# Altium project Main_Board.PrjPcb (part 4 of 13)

## Sheet SPI_Muxes.SchDoc: SPI_Muxes
size A3; Organization: Altium Limited; Address1: L3, 12a Rodborough Rd; Address2: Frenchs Forest; Address3: NSW; Address4: Australia 2086
Used 2 times, as channels HighSpeed/SPI_bridge_PCIe, SPI_bridge_Main. Parts and nets are listed once, with the designators drawn on the sheet.
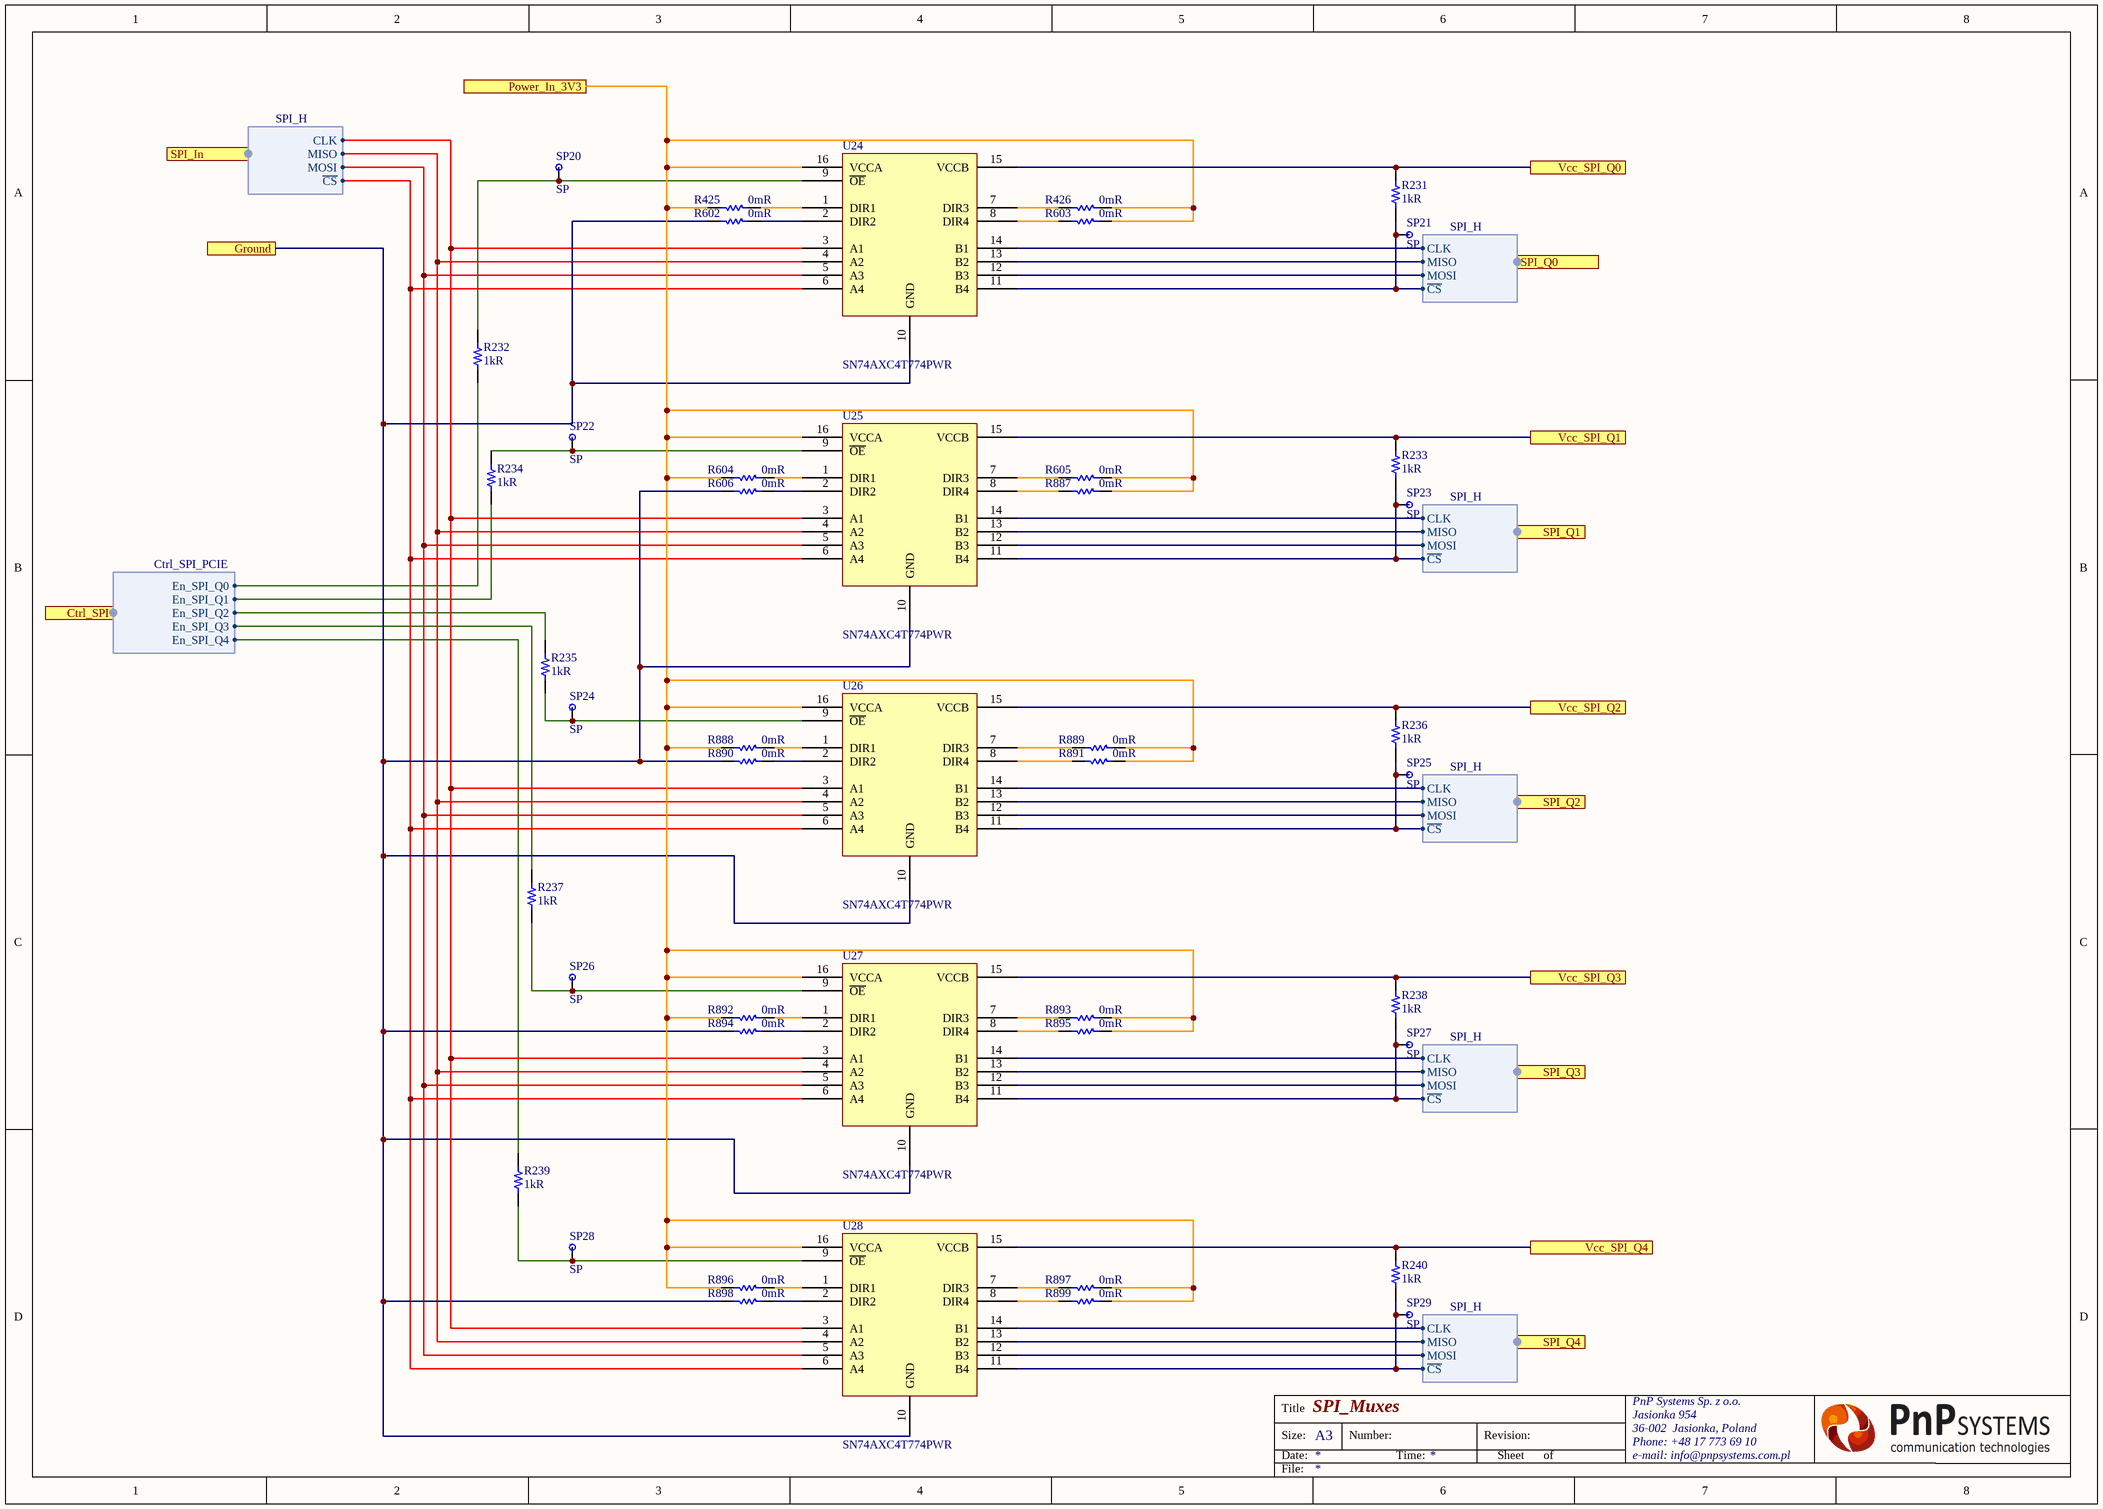
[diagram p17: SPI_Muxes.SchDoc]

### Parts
R231  1kR  [RES 0402/1005 RF KK]
R232  1kR  [RES 0402/1005 RF KK]
R233  1kR  [RES 0402/1005 RF KK]
R234  1kR  [RES 0402/1005 RF KK]
R235  1kR  [RES 0402/1005 RF KK]
R236  1kR  [RES 0402/1005 RF KK]
R237  1kR  [RES 0402/1005 RF KK]
R238  1kR  [RES 0402/1005 RF KK]
R239  1kR  [RES 0402/1005 RF KK]
R240  1kR  [RES 0402/1005 RF KK]
R425  0mR  [RES 0402/1005 RF KK]
R426  0mR  [RES 0402/1005 RF KK]
R602  0mR  [RES 0402/1005 RF KK]
R603  0mR  [RES 0402/1005 RF KK]
R604  0mR  [RES 0402/1005 RF KK]
R605  0mR  [RES 0402/1005 RF KK]
R606  0mR  [RES 0402/1005 RF KK]
R887  0mR  [RES 0402/1005 RF KK]
R888  0mR  [RES 0402/1005 RF KK]
R889  0mR  [RES 0402/1005 RF KK]
R890  0mR  [RES 0402/1005 RF KK]
R891  0mR  [RES 0402/1005 RF KK]
R892  0mR  [RES 0402/1005 RF KK]
R893  0mR  [RES 0402/1005 RF KK]
R894  0mR  [RES 0402/1005 RF KK]
R895  0mR  [RES 0402/1005 RF KK]
R896  0mR  [RES 0402/1005 RF KK]
R897  0mR  [RES 0402/1005 RF KK]
R898  0mR  [RES 0402/1005 RF KK]
R899  0mR  [RES 0402/1005 RF KK]
SP20  SP  [MeasureTP]
SP21  SP  [MeasureTP]
SP22  SP  [MeasureTP]
SP23  SP  [MeasureTP]
SP24  SP  [MeasureTP]
SP25  SP  [MeasureTP]
SP26  SP  [MeasureTP]
SP27  SP  [MeasureTP]
SP28  SP  [MeasureTP]
SP29  SP  [MeasureTP]
U24  SN74AXC4T774PWR  [SN74AXC4T774PWR]
U25  SN74AXC4T774PWR  [SN74AXC4T774PWR]
U26  SN74AXC4T774PWR  [SN74AXC4T774PWR]
U27  SN74AXC4T774PWR  [SN74AXC4T774PWR]
U28  SN74AXC4T774PWR  [SN74AXC4T774PWR]

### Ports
Ctrl_SPI (harness Ctrl_SPI_PCIE), Ground, Power_In_3V3, SPI_In (harness SPI_H), SPI_Q0 (harness SPI_H), SPI_Q1 (harness SPI_H), SPI_Q2 (harness SPI_H), SPI_Q3 (harness SPI_H), SPI_Q4 (harness SPI_H), Vcc_SPI_Q0, Vcc_SPI_Q1, Vcc_SPI_Q2, Vcc_SPI_Q3, Vcc_SPI_Q4

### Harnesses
SPI_H: CLK, MISO, MOSI, ~{CS}
Ctrl_SPI_PCIE: En_SPI_Q0, En_SPI_Q1, En_SPI_Q2, En_SPI_Q3, En_SPI_Q4

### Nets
Ground: R602.2 R606.2 R890.2 R894.2 R898.2 U24.10(GND) U25.10(GND) U26.10(GND) U27.10(GND) U28.10(GND) ; port Ground
Power_In_3V3: R425.2 R426.1 R603.1 R604.2 R605.1 R887.1 R888.2 R889.1 R891.1 R892.2 R893.1 R895.1 R896.2 R897.1 R899.1 U24.16(VCCA) U25.16(VCCA) U26.16(VCCA) U27.16(VCCA) U28.16(VCCA) ; port Power_In_3V3
Vcc_SPI_Q0: R231.2 U24.15(VCCB) ; port Vcc_SPI_Q0
Vcc_SPI_Q1: R233.2 U25.15(VCCB) ; port Vcc_SPI_Q1
Vcc_SPI_Q2: R236.2 U26.15(VCCB) ; port Vcc_SPI_Q2
Vcc_SPI_Q3: R238.2 U27.15(VCCB) ; port Vcc_SPI_Q3
Vcc_SPI_Q4: R240.2 U28.15(VCCB) ; port Vcc_SPI_Q4
NetR231_1: R231.1 SP21.1 U24.11(B4) ; port SPI_Q0.~{CS}
NetR232_1: R232.1 ; port Ctrl_SPI.En_SPI_Q0
NetR232_2: R232.2 SP20.1 U24.9(~{OE})
NetR233_1: R233.1 SP23.1 U25.11(B4) ; port SPI_Q1.~{CS}
NetR234_1: R234.1 ; port Ctrl_SPI.En_SPI_Q1
NetR234_2: R234.2 SP22.1 U25.9(~{OE})
NetR235_1: R235.1 SP24.1 U26.9(~{OE})
NetR235_2: R235.2 ; port Ctrl_SPI.En_SPI_Q2
NetR236_1: R236.1 SP25.1 U26.11(B4) ; port SPI_Q2.~{CS}
NetR237_1: R237.1 SP26.1 U27.9(~{OE})
NetR237_2: R237.2 ; port Ctrl_SPI.En_SPI_Q3
NetR238_1: R238.1 SP27.1 U27.11(B4) ; port SPI_Q3.~{CS}
NetR239_1: R239.1 ; port Ctrl_SPI.En_SPI_Q4
NetR239_2: R239.2 SP28.1 U28.9(~{OE})
NetR240_1: R240.1 SP29.1 U28.11(B4) ; port SPI_Q4.~{CS}
NetR425_1: R425.1 U24.1(DIR1)
NetR426_2: R426.2 U24.7(DIR3)
NetR602_1: R602.1 U24.2(DIR2)
NetR603_2: R603.2 U24.8(DIR4)
NetR604_1: R604.1 U25.1(DIR1)
NetR605_2: R605.2 U25.7(DIR3)
NetR606_1: R606.1 U25.2(DIR2)
NetR887_2: R887.2 U25.8(DIR4)
NetR888_1: R888.1 U26.1(DIR1)
NetR889_2: R889.2 U26.7(DIR3)
NetR890_1: R890.1 U26.2(DIR2)
NetR891_2: R891.2 U26.8(DIR4)
NetR892_1: R892.1 U27.1(DIR1)
NetR893_2: R893.2 U27.7(DIR3)
NetR894_1: R894.1 U27.2(DIR2)
NetR895_2: R895.2 U27.8(DIR4)
NetR896_1: R896.1 U28.1(DIR1)
NetR897_2: R897.2 U28.7(DIR3)
NetR898_1: R898.1 U28.2(DIR2)
NetR899_2: R899.2 U28.8(DIR4)
NetU24_3: U24.3(A1) U25.3(A1) U26.3(A1) U27.3(A1) U28.3(A1) ; port SPI_In.CLK
NetU24_4: U24.4(A2) U25.4(A2) U26.4(A2) U27.4(A2) U28.4(A2) ; port SPI_In.MISO
NetU24_5: U24.5(A3) U25.5(A3) U26.5(A3) U27.5(A3) U28.5(A3) ; port SPI_In.MOSI
NetU24_6: U24.6(A4) U25.6(A4) U26.6(A4) U27.6(A4) U28.6(A4) ; port SPI_In.~{CS}
NetU24_12: U24.12(B3) ; port SPI_Q0.MOSI
NetU24_13: U24.13(B2) ; port SPI_Q0.MISO
NetU24_14: U24.14(B1) ; port SPI_Q0.CLK
NetU25_12: U25.12(B3) ; port SPI_Q1.MOSI
NetU25_13: U25.13(B2) ; port SPI_Q1.MISO
NetU25_14: U25.14(B1) ; port SPI_Q1.CLK
NetU26_12: U26.12(B3) ; port SPI_Q2.MOSI
NetU26_13: U26.13(B2) ; port SPI_Q2.MISO
NetU26_14: U26.14(B1) ; port SPI_Q2.CLK
NetU27_12: U27.12(B3) ; port SPI_Q3.MOSI
NetU27_13: U27.13(B2) ; port SPI_Q3.MISO
NetU27_14: U27.14(B1) ; port SPI_Q3.CLK
NetU28_12: U28.12(B3) ; port SPI_Q4.MOSI
NetU28_13: U28.13(B2) ; port SPI_Q4.MISO
NetU28_14: U28.14(B1) ; port SPI_Q4.CLK

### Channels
HighSpeed/SPI_bridge_PCIe: designators end in _SPI_bridge_PCIe; ports Ground=B503_Ground Power_In_3V3=3V3_RAIL Vcc_SPI_Q0=3V3_RAIL Vcc_SPI_Q1=3V3_RAIL Vcc_SPI_Q2=3V3_RAIL Vcc_SPI_Q3=3V3_RAIL Vcc_SPI_Q4=3V3_RAIL
SPI_bridge_Main: designators end in _SPI_bridge_Main; ports Ground=B503_Ground Power_In_3V3=3V3_RAIL Vcc_SPI_Q0=3V3_RAIL Vcc_SPI_Q1=3V3_RAIL Vcc_SPI_Q2=3V3_RAIL Vcc_SPI_Q3=3V3_RAIL Vcc_SPI_Q4=3V3_RAIL

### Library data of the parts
R231-R240 = Resistor: Manufacturer: Panasonic; Manufacturer Part Number: ERJ-2RKF1001X; Tolerance: 1%; Power Rating: 100mW; Temperature Coefficient: 100ppm/°C; Voltage Rating: 50V
R425 R426 R602-R606 R887-R899 = Resistor: Manufacturer 1: Yageo; Manufacturer Part Number 1: RC0402JR-070RL; Power Rating: 62.5mW; Tolerance: 5%; Voltage Rating: 50V; Max Power Dissipation: 63mW; Temperature Coefficient: 200ppm/°C
U24-U28 = SN74AXC4T774PWR: Manufacturer 1: Texas Instruments

## Sheet Power4HiSpeed.SchDoc
size A3; Organization: Altium Limited; Address1: L3, 12a Rodborough Rd; Address2: Frenchs Forest; Address3: NSW; Address4: Australia 2086
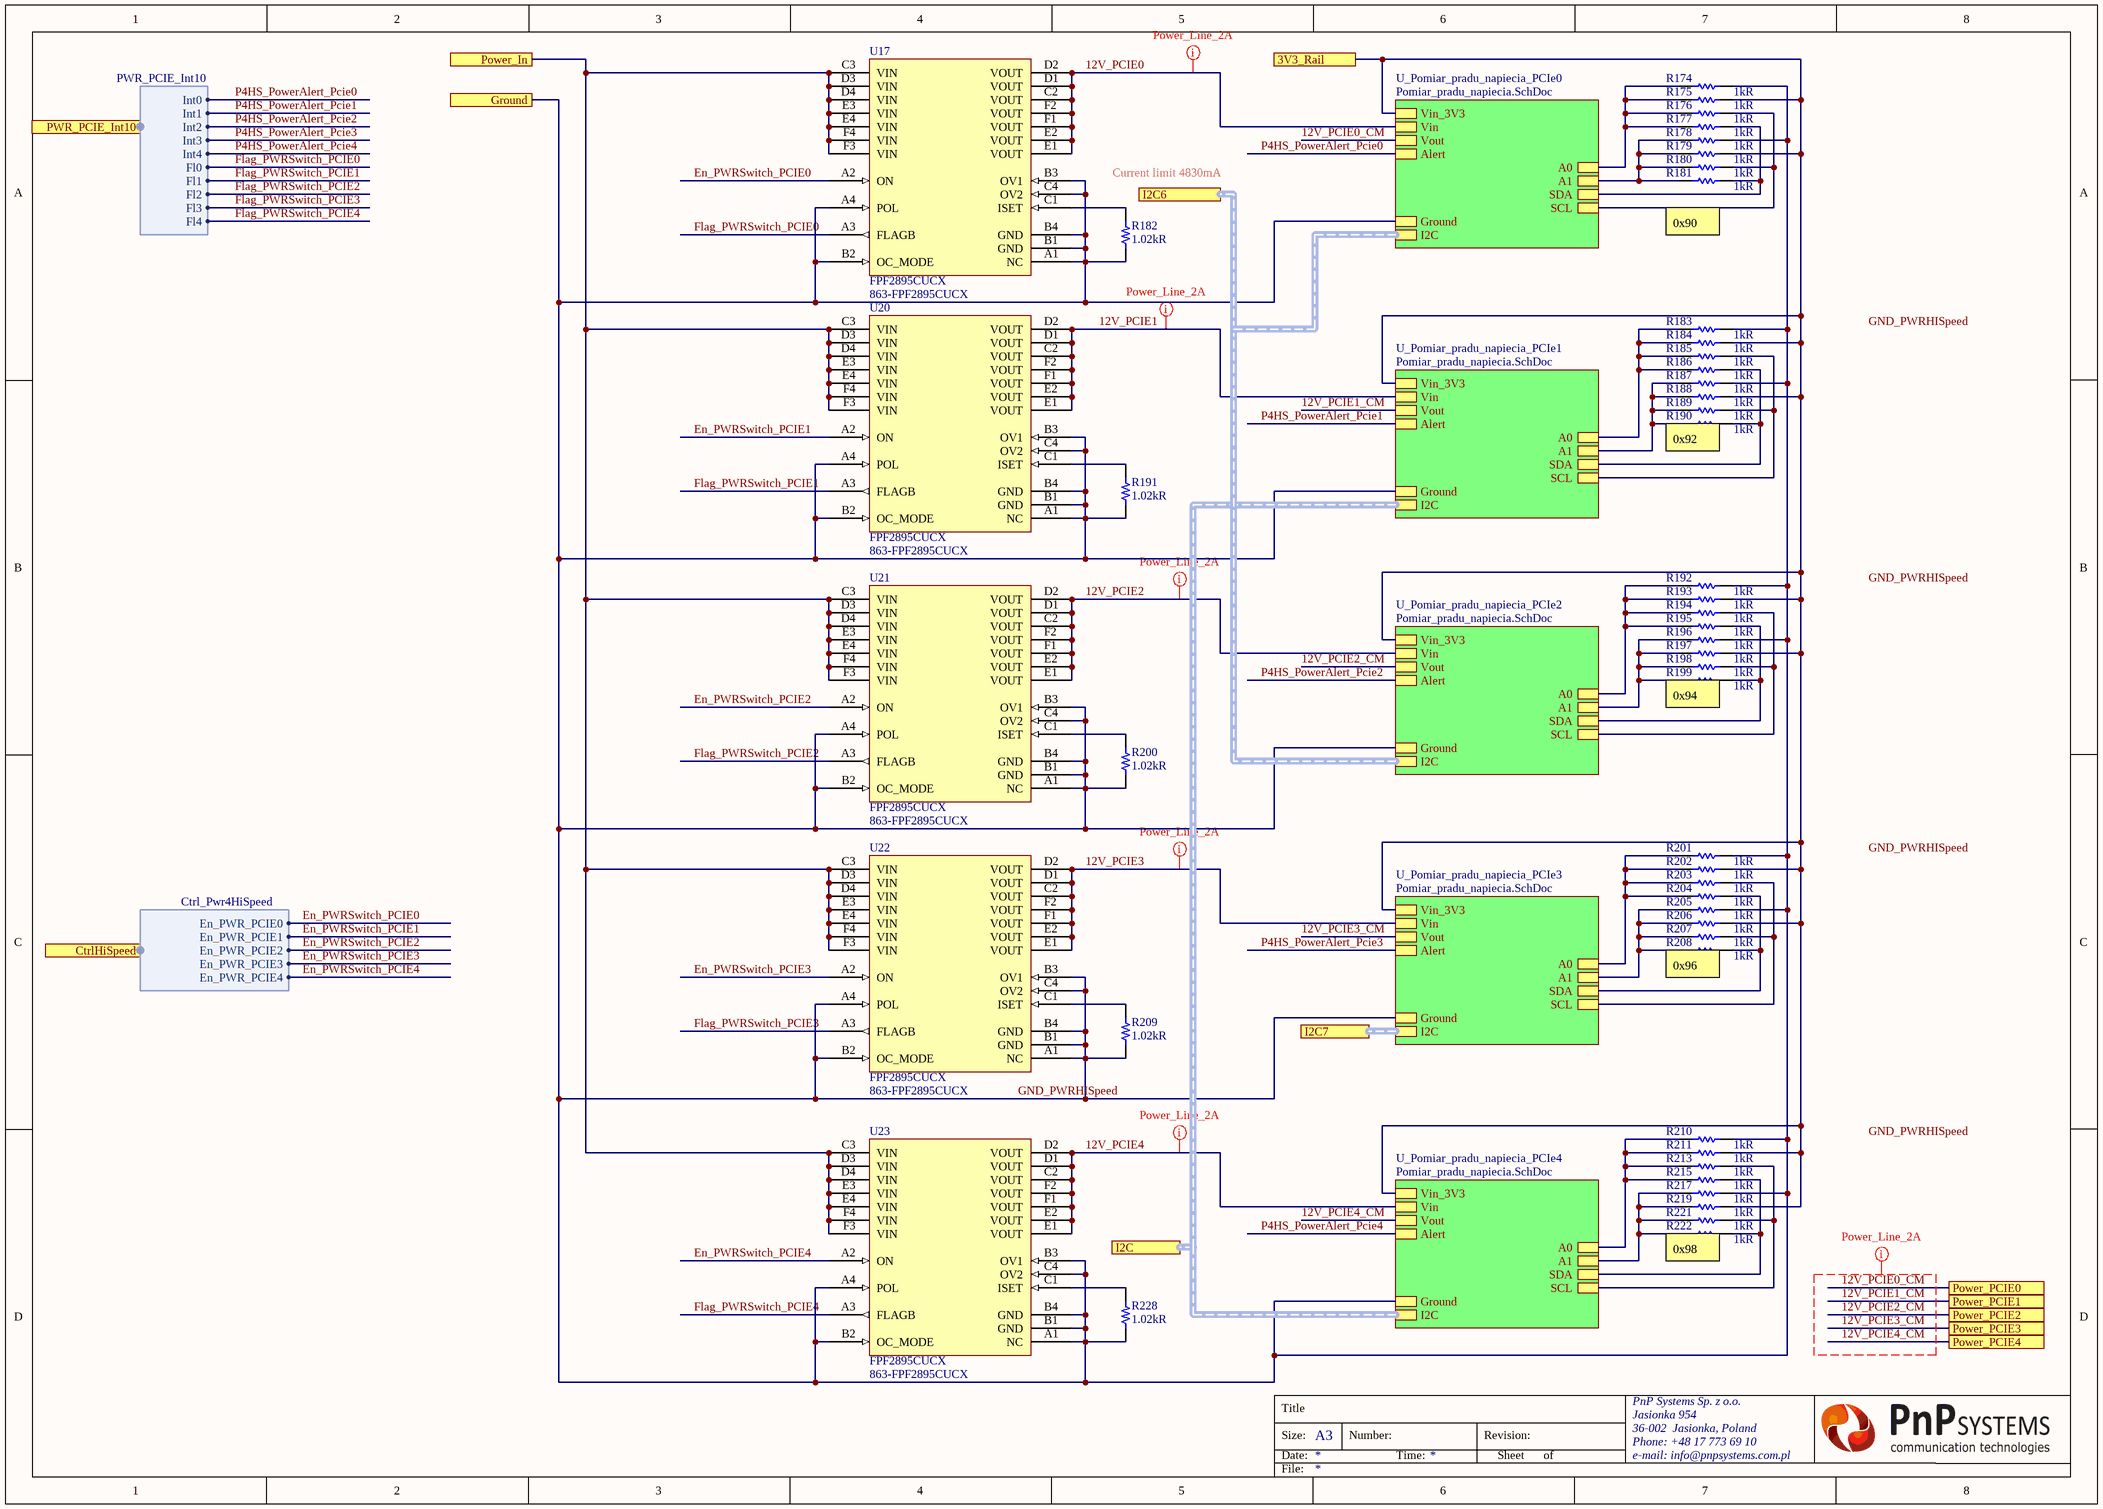
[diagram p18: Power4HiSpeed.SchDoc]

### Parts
R174  1kR  [RES 0402/1005 RF KK]
R175  1kR  [RES 0402/1005 RF KK]
R176  1kR  [RES 0402/1005 RF KK]
R177  1kR  [RES 0402/1005 RF KK]
R178  1kR  [RES 0402/1005 RF KK]
R179  1kR  [RES 0402/1005 RF KK]
R180  1kR  [RES 0402/1005 RF KK]
R181  1kR  [RES 0402/1005 RF KK]
R182  1.02kR  [RES 0402/1005 RF KK]
R183  1kR  [RES 0402/1005 RF KK]
R184  1kR  [RES 0402/1005 RF KK]
R185  1kR  [RES 0402/1005 RF KK]
R186  1kR  [RES 0402/1005 RF KK]
R187  1kR  [RES 0402/1005 RF KK]
R188  1kR  [RES 0402/1005 RF KK]
R189  1kR  [RES 0402/1005 RF KK]
R190  1kR  [RES 0402/1005 RF KK]
R191  1.02kR  [RES 0402/1005 RF KK]
R192  1kR  [RES 0402/1005 RF KK]
R193  1kR  [RES 0402/1005 RF KK]
R194  1kR  [RES 0402/1005 RF KK]
R195  1kR  [RES 0402/1005 RF KK]
R196  1kR  [RES 0402/1005 RF KK]
R197  1kR  [RES 0402/1005 RF KK]
R198  1kR  [RES 0402/1005 RF KK]
R199  1kR  [RES 0402/1005 RF KK]
R200  1.02kR  [RES 0402/1005 RF KK]
R201  1kR  [RES 0402/1005 RF KK]
R202  1kR  [RES 0402/1005 RF KK]
R203  1kR  [RES 0402/1005 RF KK]
R204  1kR  [RES 0402/1005 RF KK]
R205  1kR  [RES 0402/1005 RF KK]
R206  1kR  [RES 0402/1005 RF KK]
R207  1kR  [RES 0402/1005 RF KK]
R208  1kR  [RES 0402/1005 RF KK]
R209  1.02kR  [RES 0402/1005 RF KK]
R210  1kR  [RES 0402/1005 RF KK]
R211  1kR  [RES 0402/1005 RF KK]
R213  1kR  [RES 0402/1005 RF KK]
R215  1kR  [RES 0402/1005 RF KK]
R217  1kR  [RES 0402/1005 RF KK]
R219  1kR  [RES 0402/1005 RF KK]
R221  1kR  [RES 0402/1005 RF KK]
R222  1kR  [RES 0402/1005 RF KK]
R228  1.02kR  [RES 0402/1005 RF KK]
U17  FPF2895CUCX  Supplier Part Number 1: 863-FPF2895CUCX  [FPF2895C-D]
U20  FPF2895CUCX  Supplier Part Number 1: 863-FPF2895CUCX  [FPF2895C-D]
U21  FPF2895CUCX  Supplier Part Number 1: 863-FPF2895CUCX  [FPF2895C-D]
U22  FPF2895CUCX  Supplier Part Number 1: 863-FPF2895CUCX  [FPF2895C-D]
U23  FPF2895CUCX  Supplier Part Number 1: 863-FPF2895CUCX  [FPF2895C-D]

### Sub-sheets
U_Pomiar_pradu_napiecia_PCIe0 = Pomiar_pradu_napiecia.SchDoc: Vin_3V3, Vin, Vout, Alert, A0, A1, SDA, SCL, Ground, I2C (harness I2C)
U_Pomiar_pradu_napiecia_PCIe1 = Pomiar_pradu_napiecia.SchDoc: Vin_3V3, Vin, Vout, Alert, A0, A1, SDA, SCL, Ground, I2C (harness I2C)
U_Pomiar_pradu_napiecia_PCIe2 = Pomiar_pradu_napiecia.SchDoc: Vin_3V3, Vin, Vout, Alert, A0, A1, SDA, SCL, Ground, I2C (harness I2C)
U_Pomiar_pradu_napiecia_PCIe3 = Pomiar_pradu_napiecia.SchDoc: Vin_3V3, Vin, Vout, Alert, A0, A1, SDA, SCL, Ground, I2C (harness I2C)
U_Pomiar_pradu_napiecia_PCIe4 = Pomiar_pradu_napiecia.SchDoc: Vin_3V3, Vin, Vout, Alert, A0, A1, SDA, SCL, Ground, I2C (harness I2C)

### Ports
3V3_Rail, CtrlHiSpeed (harness Ctrl_Pwr4HiSpeed), Ground, I2C6, I2C7, I2C (harness I2C), Power_In, Power_PCIE0, Power_PCIE1, Power_PCIE2, Power_PCIE3, Power_PCIE4, PWR_PCIE_Int10 (harness PWR_PCIE_Int10)

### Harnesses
Ctrl_Pwr4HiSpeed: En_PWR_PCIE0, En_PWR_PCIE1, En_PWR_PCIE2, En_PWR_PCIE3, En_PWR_PCIE4
PWR_PCIE_Int10: Int0, Int1, Int2, Int3, Int4, Fl0, Fl1, Fl2, Fl3, Fl4

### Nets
GND_PWRHISpeed: R174.2 R178.2 R182.1 R183.2 R187.2 R191.1 R192.2 R196.2 R200.1 R201.2 R205.2 R209.1 R210.2 R217.2 R228.1 U17.A1(NC) U17.A4(POL) U17.B1(GND) U17.B2(OC_MODE) U17.B3(OV1) U17.B4(GND) U17.C4(OV2) U20.A1(NC) U20.A4(POL) U20.B1(GND) U20.B2(OC_MODE) U20.B3(OV1) U20.B4(GND) U20.C4(OV2) U21.A1(NC) U21.A4(POL) U21.B1(GND) U21.B2(OC_MODE) U21.B3(OV1) U21.B4(GND) U21.C4(OV2) U22.A1(NC) U22.A4(POL) U22.B1(GND) U22.B2(OC_MODE) U22.B3(OV1) U22.B4(GND) U22.C4(OV2) U23.A1(NC) U23.A4(POL) U23.B1(GND) U23.B2(OC_MODE) U23.B3(OV1) U23.B4(GND) U23.C4(OV2) ; port Ground, sheet U_Pomiar_pradu_napiecia_PCIe0/Ground, sheet U_Pomiar_pradu_napiecia_PCIe1/Ground, sheet U_Pomiar_pradu_napiecia_PCIe2/Ground, sheet U_Pomiar_pradu_napiecia_PCIe3/Ground, sheet U_Pomiar_pradu_napiecia_PCIe4/Ground  [project net B503_Ground]
3V3_RAIL: R175.2 R179.2 R184.2 R188.2 R193.2 R197.2 R202.2 R206.2 R211.2 R219.2 ; port 3V3_Rail, sheet U_Pomiar_pradu_napiecia_PCIe0/Vin_3V3, sheet U_Pomiar_pradu_napiecia_PCIe1/Vin_3V3, sheet U_Pomiar_pradu_napiecia_PCIe2/Vin_3V3, sheet U_Pomiar_pradu_napiecia_PCIe3/Vin_3V3, sheet U_Pomiar_pradu_napiecia_PCIe4/Vin_3V3
12V_LT3042: U17.C3(VIN) U17.D3(VIN) U17.D4(VIN) U17.E3(VIN) U17.E4(VIN) U17.F3(VIN) U17.F4(VIN) U20.C3(VIN) U20.D3(VIN) U20.D4(VIN) U20.E3(VIN) U20.E4(VIN) U20.F3(VIN) U20.F4(VIN) U21.C3(VIN) U21.D3(VIN) U21.D4(VIN) U21.E3(VIN) U21.E4(VIN) U21.F3(VIN) U21.F4(VIN) U22.C3(VIN) U22.D3(VIN) U22.D4(VIN) U22.E3(VIN) U22.E4(VIN) U22.F3(VIN) U22.F4(VIN) U23.C3(VIN) U23.D3(VIN) U23.D4(VIN) U23.E3(VIN) U23.E4(VIN) U23.F3(VIN) U23.F4(VIN) ; port Power_In
12V_PCIE0: U17.C2(VOUT) U17.D1(VOUT) U17.D2(VOUT) U17.E1(VOUT) U17.E2(VOUT) U17.F1(VOUT) U17.F2(VOUT) ; sheet U_Pomiar_pradu_napiecia_PCIe0/Vin
12V_PCIE0_CM: port Power_PCIE0, sheet U_Pomiar_pradu_napiecia_PCIe0/Vout
12V_PCIE1: U20.C2(VOUT) U20.D1(VOUT) U20.D2(VOUT) U20.E1(VOUT) U20.E2(VOUT) U20.F1(VOUT) U20.F2(VOUT) ; sheet U_Pomiar_pradu_napiecia_PCIe1/Vin
12V_PCIE1_CM: port Power_PCIE1, sheet U_Pomiar_pradu_napiecia_PCIe1/Vout
12V_PCIE2: U21.C2(VOUT) U21.D1(VOUT) U21.D2(VOUT) U21.E1(VOUT) U21.E2(VOUT) U21.F1(VOUT) U21.F2(VOUT) ; sheet U_Pomiar_pradu_napiecia_PCIe2/Vin
12V_PCIE2_CM: port Power_PCIE2, sheet U_Pomiar_pradu_napiecia_PCIe2/Vout
12V_PCIE3: U22.C2(VOUT) U22.D1(VOUT) U22.D2(VOUT) U22.E1(VOUT) U22.E2(VOUT) U22.F1(VOUT) U22.F2(VOUT) ; sheet U_Pomiar_pradu_napiecia_PCIe3/Vin
12V_PCIE3_CM: port Power_PCIE3, sheet U_Pomiar_pradu_napiecia_PCIe3/Vout
12V_PCIE4: U23.C2(VOUT) U23.D1(VOUT) U23.D2(VOUT) U23.E1(VOUT) U23.E2(VOUT) U23.F1(VOUT) U23.F2(VOUT) ; sheet U_Pomiar_pradu_napiecia_PCIe4/Vin
12V_PCIE4_CM: port Power_PCIE4, sheet U_Pomiar_pradu_napiecia_PCIe4/Vout
En_PWRSwitch_PCIE0: U17.A2(ON) ; port CtrlHiSpeed.En_PWR_PCIE0
En_PWRSwitch_PCIE1: U20.A2(ON) ; port CtrlHiSpeed.En_PWR_PCIE1
En_PWRSwitch_PCIE2: U21.A2(ON) ; port CtrlHiSpeed.En_PWR_PCIE2
En_PWRSwitch_PCIE3: U22.A2(ON) ; port CtrlHiSpeed.En_PWR_PCIE3  [project net EN_PWR_PCIE_3]
En_PWRSwitch_PCIE4: U23.A2(ON) ; port CtrlHiSpeed.En_PWR_PCIE4  [project net EN_PWR_PCIE_4]
Flag_PWRSwitch_PCIE0: U17.A3(FLAGB) ; port PWR_PCIE_Int10.Fl0
Flag_PWRSwitch_PCIE1: U20.A3(FLAGB) ; port PWR_PCIE_Int10.Fl1
Flag_PWRSwitch_PCIE2: U21.A3(FLAGB) ; port PWR_PCIE_Int10.Fl2
Flag_PWRSwitch_PCIE3: U22.A3(FLAGB) ; port PWR_PCIE_Int10.Fl3
Flag_PWRSwitch_PCIE4: U23.A3(FLAGB) ; port PWR_PCIE_Int10.Fl4
HiSpeedModule_I2C0.SCL: R185.2 R189.2 R213.2 R221.2 ; sheet U_Pomiar_pradu_napiecia_PCIe1/SCL, sheet U_Pomiar_pradu_napiecia_PCIe4/SCL
HiSpeedModule_I2C0.SDA: R186.2 R190.2 R215.2 R222.2 ; sheet U_Pomiar_pradu_napiecia_PCIe1/SDA, sheet U_Pomiar_pradu_napiecia_PCIe4/SDA
HiSpeedModule_I2C6.SCL: R176.2 R180.2 R194.2 R198.2 ; sheet U_Pomiar_pradu_napiecia_PCIe0/SCL, sheet U_Pomiar_pradu_napiecia_PCIe2/SCL
HiSpeedModule_I2C6.SDA: R177.2 R181.2 R195.2 R199.2 ; sheet U_Pomiar_pradu_napiecia_PCIe0/SDA, sheet U_Pomiar_pradu_napiecia_PCIe2/SDA
HiSpeedModule_I2C7.SCL: R203.2 R207.2 ; sheet U_Pomiar_pradu_napiecia_PCIe3/SCL
HiSpeedModule_I2C7.SDA: R204.2 R208.2 ; sheet U_Pomiar_pradu_napiecia_PCIe3/SDA
P4HS_PowerAlert_Pcie0: sheet U_Pomiar_pradu_napiecia_PCIe0/Alert, port PWR_PCIE_Int10.Int0
P4HS_PowerAlert_Pcie1: sheet U_Pomiar_pradu_napiecia_PCIe1/Alert, port PWR_PCIE_Int10.Int1
P4HS_PowerAlert_Pcie2: sheet U_Pomiar_pradu_napiecia_PCIe2/Alert, port PWR_PCIE_Int10.Int2
P4HS_PowerAlert_Pcie3: sheet U_Pomiar_pradu_napiecia_PCIe3/Alert, port PWR_PCIE_Int10.Int3
P4HS_PowerAlert_Pcie4: sheet U_Pomiar_pradu_napiecia_PCIe4/Alert, port PWR_PCIE_Int10.Int4
NetR174_1: R174.1 R175.1 R176.1 R177.1 ; sheet U_Pomiar_pradu_napiecia_PCIe0/A0
NetR178_1: R178.1 R179.1 R180.1 R181.1 ; sheet U_Pomiar_pradu_napiecia_PCIe0/A1
NetR182_2: R182.2 U17.C1(ISET)
NetR183_1: R183.1 R184.1 R185.1 R186.1 ; sheet U_Pomiar_pradu_napiecia_PCIe1/A0
NetR187_1: R187.1 R188.1 R189.1 R190.1 ; sheet U_Pomiar_pradu_napiecia_PCIe1/A1
NetR191_2: R191.2 U20.C1(ISET)
NetR192_1: R192.1 R193.1 R194.1 R195.1 ; sheet U_Pomiar_pradu_napiecia_PCIe2/A0
NetR196_1: R196.1 R197.1 R198.1 R199.1 ; sheet U_Pomiar_pradu_napiecia_PCIe2/A1
NetR200_2: R200.2 U21.C1(ISET)
NetR201_1: R201.1 R202.1 R203.1 R204.1 ; sheet U_Pomiar_pradu_napiecia_PCIe3/A0
NetR205_1: R205.1 R206.1 R207.1 R208.1 ; sheet U_Pomiar_pradu_napiecia_PCIe3/A1
NetR209_2: R209.2 U22.C1(ISET)
NetR210_1: R210.1 R211.1 R213.1 R215.1 ; sheet U_Pomiar_pradu_napiecia_PCIe4/A0
NetR217_1: R217.1 R219.1 R221.1 R222.1 ; sheet U_Pomiar_pradu_napiecia_PCIe4/A1
NetR228_2: R228.2 U23.C1(ISET)

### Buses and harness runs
harness port I2C6 = sheet U_Pomiar_pradu_napiecia_PCIe0/I2C = sheet U_Pomiar_pradu_napiecia_PCIe2/I2C
harness port I2C7 = sheet U_Pomiar_pradu_napiecia_PCIe3/I2C
harness port I2C = sheet U_Pomiar_pradu_napiecia_PCIe1/I2C = sheet U_Pomiar_pradu_napiecia_PCIe4/I2C

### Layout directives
net class Power_Line_2A: 12V_PCIE0, 12V_PCIE0_CM, 12V_PCIE1, 12V_PCIE1_CM, 12V_PCIE2, 12V_PCIE2_CM, 12V_PCIE3, 12V_PCIE3_CM, 12V_PCIE4, 12V_PCIE4_CM

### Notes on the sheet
- (near R182) Current limit 4830mA
- 0x90
- (near R190) 0x92
- (near R199) 0x94
- (near R208) 0x96
- (near R222) 0x98
- Labels drawn without touching a wire or pin: GND_PWRHISpeed

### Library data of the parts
R174-R181 R183-R190 R192-R199 R201-R208 R210 R211 R213 R215 R217 R219 R221 R222 = Resistor: PANASONIC - ERJ-2RKF1001X - SMD Chip Resistor, 0402 [1005 Metric], 1 kohm, ERJ2R Series, 50 V, Thick Film, 100 mW; Voltage Rating (DC): 50V; Temperature Coefficient: 100ppm/°C; Tolerance: 1%; Power Rating: 100mW
R182 R191 R200 R209 R228 = Resistor: Manufacturer: Panasonic; Manufacturer Part Number: ERJ-2RKF1021X; Tolerance: 1%; Temperature Coefficient: 100ppm/°C; Power Rating: 100mW; Voltage Rating: 50V
U17 U20-U23 = FPF2895CUCX: Current Limit Load Switch with OVP and TRCB, 28 V, 5 A; Manufacturer 1: ON Semiconductor

## Sheet Pomiar_pradu_napiecia.SchDoc: Pomiar prądu
size A3
Used 11 times, as channels HighSpeed/Power4HighSpeed/U_Pomiar_pradu_napiecia_PCIe0, HighSpeed/Power4HighSpeed/U_Pomiar_pradu_napiecia_PCIe1, HighSpeed/Power4HighSpeed/U_Pomiar_pradu_napiecia_PCIe2, HighSpeed/Power4HighSpeed/U_Pomiar_pradu_napiecia_PCIe3, HighSpeed/Power4HighSpeed/U_Pomiar_pradu_napiecia_PCIe4, PowerDistribition/HiCurrent/U_Pomiar_pradu_napiecia_3, PowerDistribition/HiCurrent/U_Pomiar_pradu_napiecia_4, PowerDistribition/HiCurrent/U_Pomiar_pradu_napiecia_5, PowerDistribition/HiCurrent/U_Pomiar_pradu_napiecia_6, PowerDistribition/U_Pomiar_pradu_napiecia_1, PowerDistribition/U_Pomiar_pradu_napiecia_2. Parts and nets are listed once, with the designators drawn on the sheet.
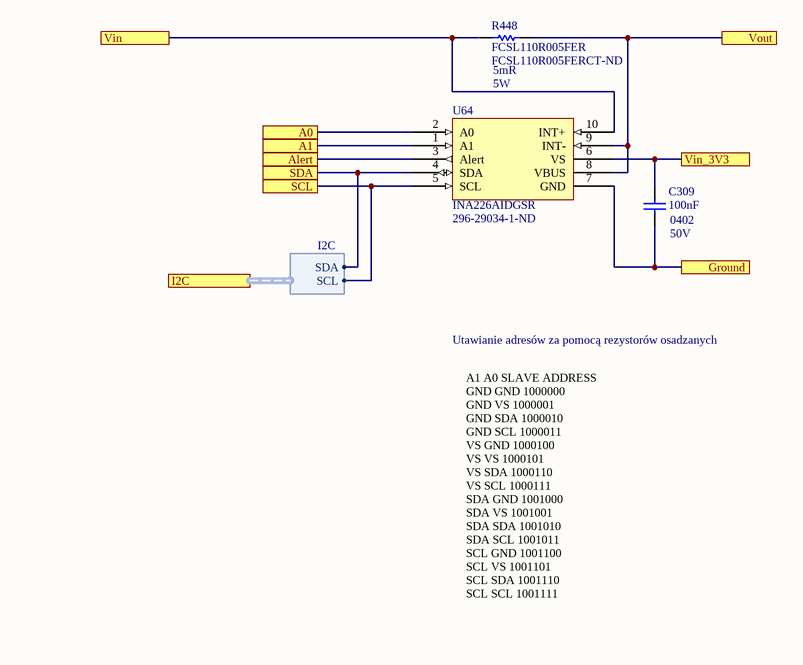
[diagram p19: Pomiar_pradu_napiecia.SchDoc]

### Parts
C309  100nF  Case Code (Imperial): 0402  Voltage: 50V  [CAP 0402/1005 KK]
R448  FCSL110R005FER  Max Power Dissipation: 5W  Resistance: 5mR  [FCSL110R005FERCT-ND]
U64  INA226AIDGSR  Supplier Part Number 1: 296-29034-1-ND  [INA226]

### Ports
A0, A1, Alert, Ground, I2C (harness I2C), SCL, SDA, Vin, Vin_3V3, Vout

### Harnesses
I2C: SCL, SDA

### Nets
A0: U64.2(A0) ; port A0
A1: U64.1(A1) ; port A1
Alert: U64.3(Alert) ; port Alert
Ground: C309.1 U64.7(GND) ; port Ground
SCL: U64.5(SCL) ; port SCL, port I2C.SCL
SDA: U64.4(SDA) ; port SDA, port I2C.SDA
Vin: R448.1 U64.10(INT+) ; port Vin
Vin_3V3: C309.2 U64.6(VS) ; port Vin_3V3
Vout: R448.2 U64.8(VBUS) U64.9(INT-) ; port Vout

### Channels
HighSpeed/Power4HighSpeed/U_Pomiar_pradu_napiecia_PCIe0: designators end in _U_Pomiar_pradu_napiecia_PCIe0; ports A0=NetR174_1 A1=NetR178_1 Alert=P4HS_PowerAlert_Pcie0 Ground=B503_Ground SCL=HiSpeedModule_I2C6.SCL SDA=HiSpeedModule_I2C6.SDA Vin=12V_PCIE0 Vin_3V3=3V3_RAIL Vout=12V_PCIE0_CM
HighSpeed/Power4HighSpeed/U_Pomiar_pradu_napiecia_PCIe1: designators end in _U_Pomiar_pradu_napiecia_PCIe1; ports A0=NetR183_1 A1=NetR187_1 Alert=P4HS_PowerAlert_Pcie1 Ground=B503_Ground SCL=HiSpeedModule_I2C0.SCL SDA=HiSpeedModule_I2C0.SDA Vin=12V_PCIE1 Vin_3V3=3V3_RAIL Vout=12V_PCIE1_CM
HighSpeed/Power4HighSpeed/U_Pomiar_pradu_napiecia_PCIe2: designators end in _U_Pomiar_pradu_napiecia_PCIe2; ports A0=NetR192_1 A1=NetR196_1 Alert=P4HS_PowerAlert_Pcie2 Ground=B503_Ground SCL=HiSpeedModule_I2C6.SCL SDA=HiSpeedModule_I2C6.SDA Vin=12V_PCIE2 Vin_3V3=3V3_RAIL Vout=12V_PCIE2_CM
HighSpeed/Power4HighSpeed/U_Pomiar_pradu_napiecia_PCIe3: designators end in _U_Pomiar_pradu_napiecia_PCIe3; ports A0=NetR201_1 A1=NetR205_1 Alert=P4HS_PowerAlert_Pcie3 Ground=B503_Ground SCL=HiSpeedModule_I2C7.SCL SDA=HiSpeedModule_I2C7.SDA Vin=12V_PCIE3 Vin_3V3=3V3_RAIL Vout=12V_PCIE3_CM
HighSpeed/Power4HighSpeed/U_Pomiar_pradu_napiecia_PCIe4: designators end in _U_Pomiar_pradu_napiecia_PCIe4; ports A0=NetR210_1 A1=NetR217_1 Alert=P4HS_PowerAlert_Pcie4 Ground=B503_Ground SCL=HiSpeedModule_I2C0.SCL SDA=HiSpeedModule_I2C0.SDA Vin=12V_PCIE4 Vin_3V3=3V3_RAIL Vout=12V_PCIE4_CM
PowerDistribition/HiCurrent/U_Pomiar_pradu_napiecia_3: designators end in _U_Pomiar_pradu_napiecia_3; ports A0=NetR561_1 A1=NetR565_1 Alert=NetR860_2 Ground=B503_Ground SCL=SFP_I2C5.SCL SDA=SFP_I2C5.SDA Vin=Vout1_1 Vin_3V3=3V3_RAIL Vout=3V3_RAIL
PowerDistribition/HiCurrent/U_Pomiar_pradu_napiecia_4: designators end in _U_Pomiar_pradu_napiecia_4; ports A0=NetR569_1 A1=NetR573_1 Alert=NetR862_2 Ground=B503_Ground SCL=SFP_I2C5.SCL SDA=SFP_I2C5.SDA Vin=Vout2_1 Vin_3V3=3V3_RAIL Vout=RAM_Vcc1V2
PowerDistribition/HiCurrent/U_Pomiar_pradu_napiecia_5: designators end in _U_Pomiar_pradu_napiecia_5; ports A0=NetR577_1 A1=NetR581_1 Alert=NetR863_2 Ground=B503_Ground SCL=SFP_I2C5.SCL SDA=SFP_I2C5.SDA Vin=Vout1_2 Vin_3V3=3V3_RAIL Vout=12V_LT3042
PowerDistribition/HiCurrent/U_Pomiar_pradu_napiecia_6: designators end in _U_Pomiar_pradu_napiecia_6; ports A0=NetR585_1 A1=NetR589_1 Alert=NetR864_2 Ground=B503_Ground SCL=SFP_I2C5.SCL SDA=SFP_I2C5.SDA Vin=Vout2_2 Vin_3V3=3V3_RAIL Vout=5V_RAIL
PowerDistribition/U_Pomiar_pradu_napiecia_1: designators end in _U_Pomiar_pradu_napiecia_1; ports A0=NetR229_1 A1=NetR461_1 Alert=PWR_PowerAlert0 Ground=B503_Ground SCL=SFP_I2C5.SCL SDA=SFP_I2C5.SDA Vin=Power1_In Vin_3V3=3V3_RAIL Vout=Power1_In_CM
PowerDistribition/U_Pomiar_pradu_napiecia_2: designators end in _U_Pomiar_pradu_napiecia_2; ports A0=NetR467_1 A1=NetR595_1 Alert=PWR_PowerAlert1 Ground=B503_Ground SCL=SFP_I2C5.SCL SDA=SFP_I2C5.SDA Vin=Power2_In Vin_3V3=3V3_RAIL Vout=Power2_In_CM

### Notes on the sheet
- Utawianie adresów za pomocą rezystorów osadzanych
- A1 A0 SLAVE ADDRESS
  GND GND 1000000
  GND VS 1000001
  GND SDA 1000010
  GND SCL 1000011
  VS GND 1000100
  VS VS 1000101
  VS SDA 1000110
  VS SCL 1000111
  SDA GND 1001000
  SDA VS 1001001
  SDA SDA 1001010
  SDA SCL 1001011
  SCL GND 1001100
  SCL VS 1001101
  SCL SDA 1001110
  SCL SCL 1001111

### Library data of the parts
C309 = Capacitor: CAP CER 0.1UF 50V X5R 0402; Manufacturer: Murata; Manufacturer Part Number: GRM155R61H104KE14D; Dielectric Material: Ceramic; Dissipation Factor: 0.025%; Tolerance: 10%
R448 = FCSL110R005FER: RES SMD 5 MOHM 5W 4320 WIDE; Manufacturer: Ohmite; Tolerance: 1%; Temperature Coefficient: 50ppm/°C
U64 = INA226AIDGSR: IC MONITOR PWR/CURR BIDIR 10MSOP; Manufacturer: Texas Instruments; Min Supply Voltage: 2.7V; Max Supply Voltage: 5.5V; Nominal Supply Current: 330uA; Common Mode Rejection Ratio: 140dB; Output Current: 10mA; Input Bias Current: 10uA; Input Offset Voltage (Vos): 2.5uV; Accuracy: 0.02%

## Sheet Power_Distribution.SchDoc: Power Distributions
size A3; Organization: Altium Limited; Address1: L3, 12a Rodborough Rd; Address2: Frenchs Forest; Address3: NSW; Address4: Australia 2086
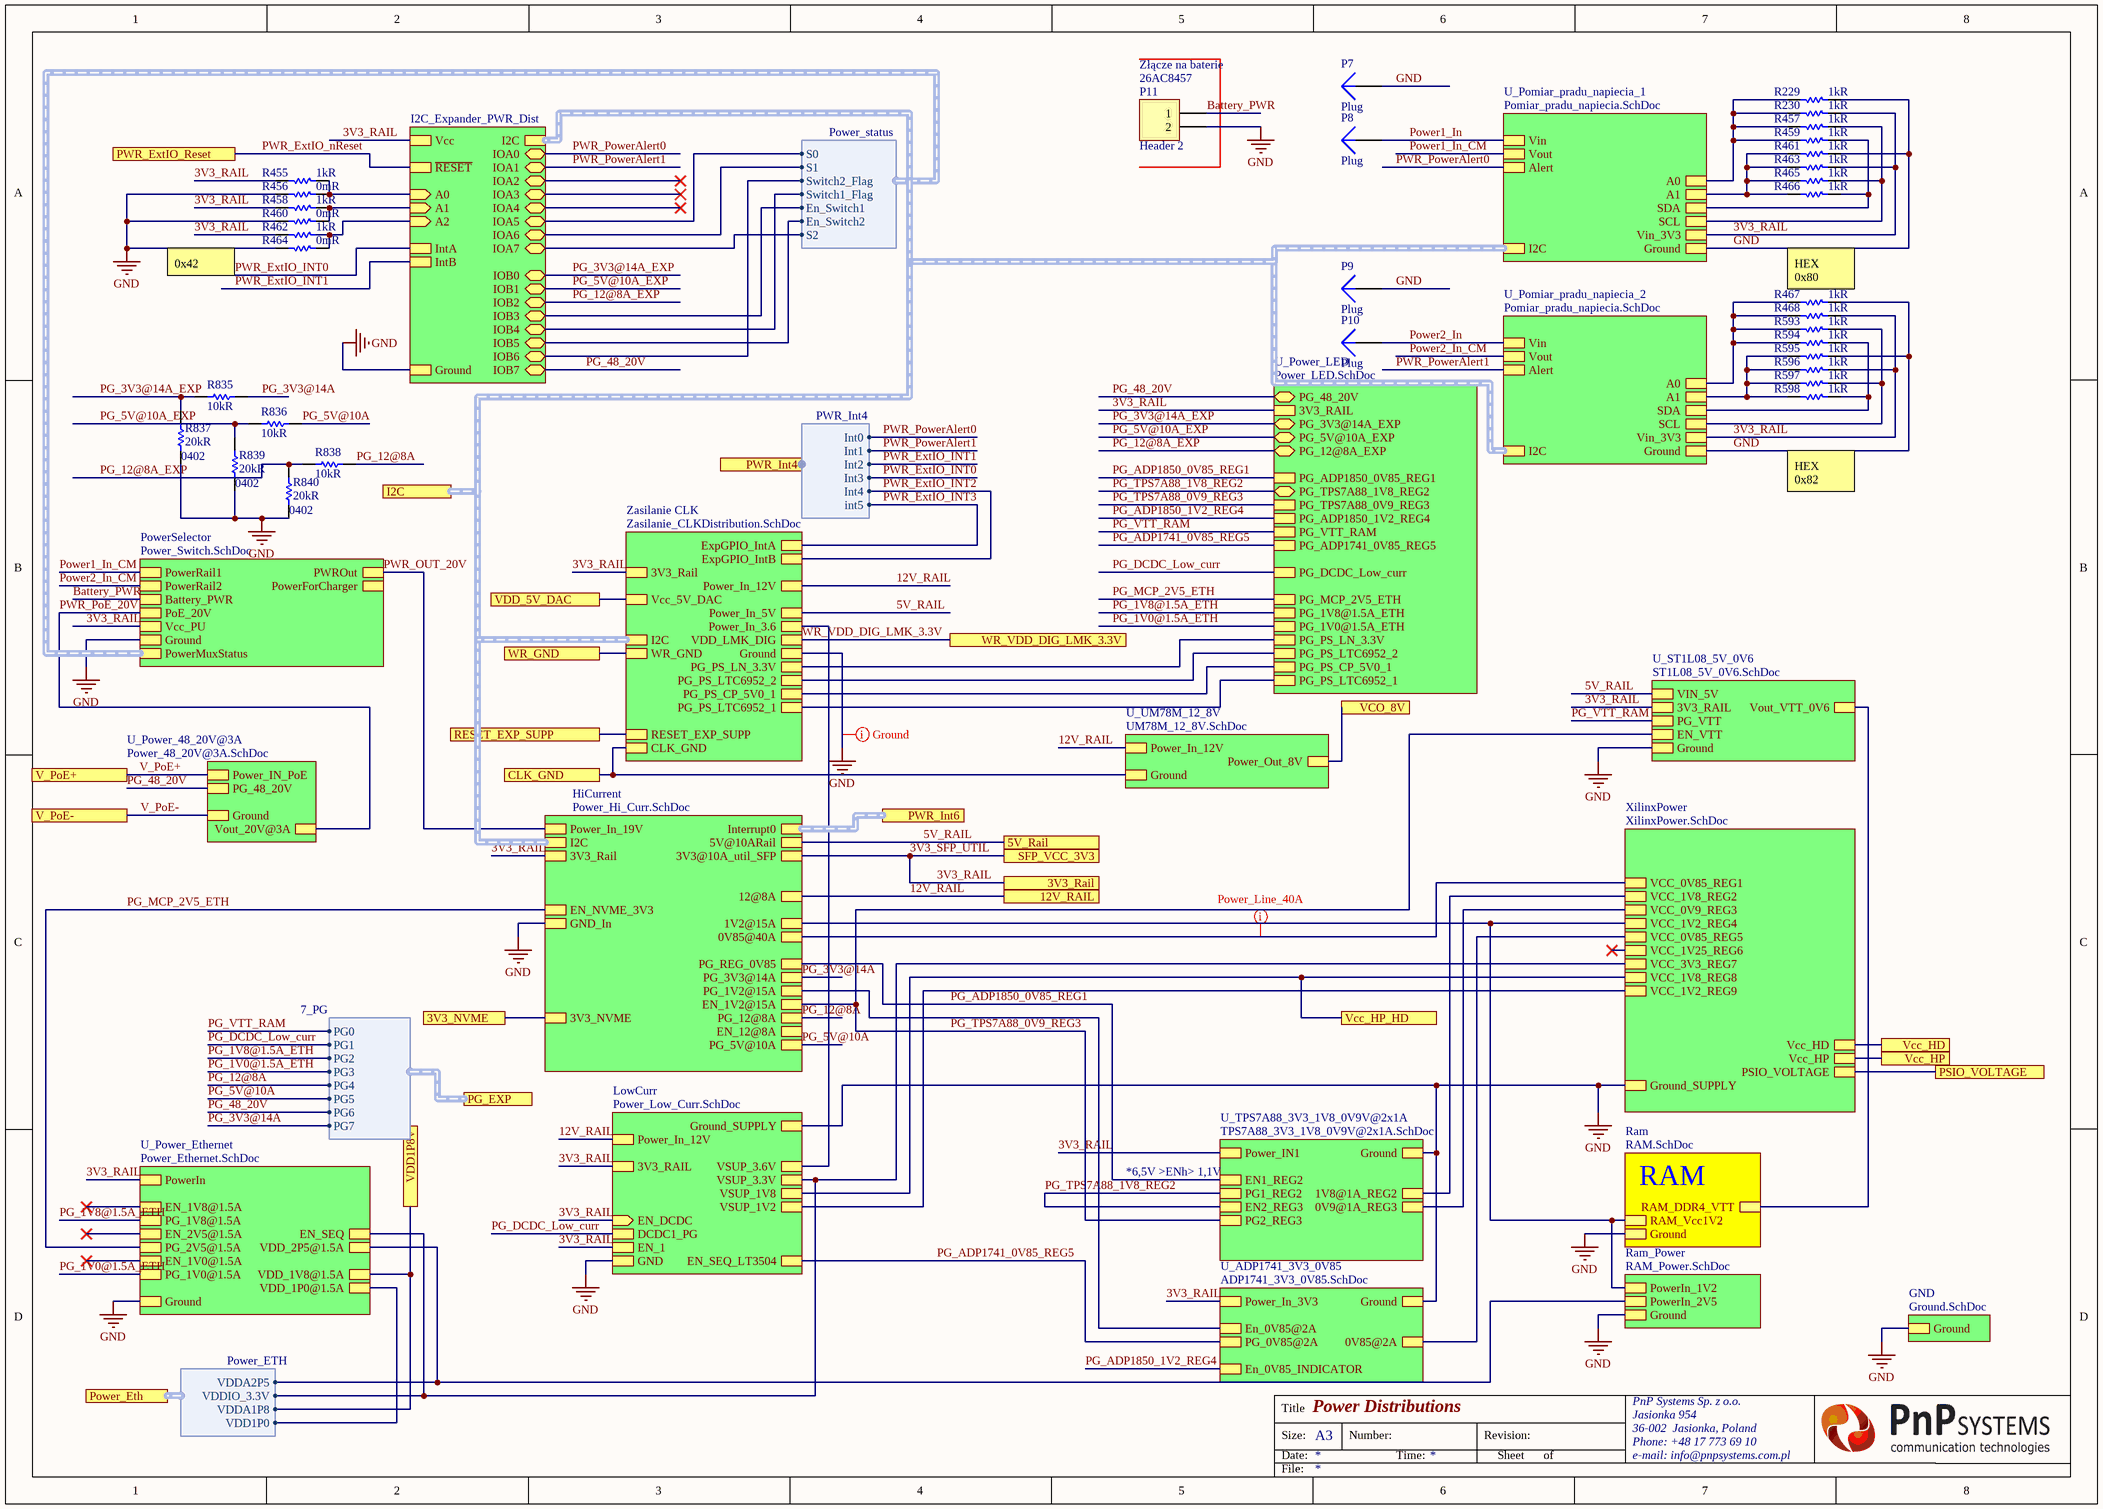
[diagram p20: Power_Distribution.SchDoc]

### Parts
P7  Plug  [PIN1]
P8  Plug  [PIN1]
P9  Plug  [PIN1]
P10  Plug  [PIN1]
P11  Header 2  Supplier Part Number 1: 26AC8457  [HDR1X2]
R229  1kR  [RES 0402/1005 RF KK]
R230  1kR  [RES 0402/1005 RF KK]
R455  1kR  [RES 0402/1005 RF KK]
R456  0mR  [RES 0402/1005 RF KK]
R457  1kR  [RES 0402/1005 RF KK]
R458  1kR  [RES 0402/1005 RF KK]
R459  1kR  [RES 0402/1005 RF KK]
R460  0mR  [RES 0402/1005 RF KK]
R461  1kR  [RES 0402/1005 RF KK]
R462  1kR  [RES 0402/1005 RF KK]
R463  1kR  [RES 0402/1005 RF KK]
R464  0mR  [RES 0402/1005 RF KK]
R465  1kR  [RES 0402/1005 RF KK]
R466  1kR  [RES 0402/1005 RF KK]
R467  1kR  [RES 0402/1005 RF KK]
R468  1kR  [RES 0402/1005 RF KK]
R593  1kR  [RES 0402/1005 RF KK]
R594  1kR  [RES 0402/1005 RF KK]
R595  1kR  [RES 0402/1005 RF KK]
R596  1kR  [RES 0402/1005 RF KK]
R597  1kR  [RES 0402/1005 RF KK]
R598  1kR  [RES 0402/1005 RF KK]
R835  10kR  [RES 0402/1005 RF KK]
R836  10kR  [RES 0402/1005 RF KK]
R837  20kR  Case/Package: 0402  [RES 0402/1005 RF KK]
R838  10kR  [RES 0402/1005 RF KK]
R839  20kR  Case/Package: 0402  [RES 0402/1005 RF KK]
R840  20kR  Case/Package: 0402  [RES 0402/1005 RF KK]

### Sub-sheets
GND = Ground.SchDoc: Ground
HiCurrent = Power_Hi_Curr.SchDoc: 0V85@40A, 1V2@15A, 3V3@10A_util_SFP, 12@8A, Power_In_19V, GND_In, I2C (harness PWR_Int4), 5V@10ARail, 3V3_Rail, Interrupt0 (harness PWR_Interrupt), EN_NVME_3V3, 3V3_NVME, PG_12@8A, PG_1V2@15A, PG_5V@10A, PG_REG_0V85, EN_1V2@15A, EN_12@8A, PG_3V3@14A
I2C_Expander_PWR_Dist = I2C_Expander.SchDoc: IOA7 (bidir), IOA3 (bidir), IOA6 (bidir), IOA1 (bidir), IOA0 (bidir), IOA5 (bidir), IOB1 (bidir), IOB2 (bidir), IOB5 (bidir), IOB6 (bidir), IOB7 (bidir), IntA, IntB, Ground, IOB4 (bidir), IOB3 (bidir), IOA2 (bidir), IOA4 (bidir), IOB0 (bidir), Vcc, ~{RESET}, I2C (harness PWR_Int4), A2 (in), A1 (in), A0 (in)
LowCurr = Power_Low_Curr.SchDoc: Power_In_12V, Ground_SUPPLY, DCDC1_PG, EN_1, VSUP_3.6V, VSUP_3.3V, VSUP_1V8, VSUP_1V2, 3V3_RAIL, GND, EN_DCDC (in), EN_SEQ_LT3504
PowerSelector = Power_Switch.SchDoc: PWROut, Battery_PWR, PowerRail2, PowerRail1, PowerMuxStatus (harness Power_status), Vcc_PU, PowerForCharger, Ground, PoE_20V
Ram = RAM.SchDoc: RAM_DDR4_VTT, RAM_Vcc1V2, Ground
Ram_Power = RAM_Power.SchDoc: PowerIn_1V2, Ground, PowerIn_2V5
U_ADP1741_3V3_0V85 = ADP1741_3V3_0V85.SchDoc: Power_In_3V3, 0V85@2A, En_0V85@2A, PG_0V85@2A, Ground, En_0V85_INDICATOR
U_Pomiar_pradu_napiecia_1 = Pomiar_pradu_napiecia.SchDoc: Vin_3V3, Vin, Vout, Alert, A0, A1, SDA, SCL, Ground, I2C (harness PWR_Int4)
U_Pomiar_pradu_napiecia_2 = Pomiar_pradu_napiecia.SchDoc: Vin_3V3, Vin, Vout, Alert, A0, A1, SDA, SCL, Ground, I2C (harness PWR_Int4)
U_Power_48_20V@3A = Power_48_20V@3A.SchDoc: Ground, Power_IN_PoE, Vout_20V@3A, PG_48_20V
U_Power_Ethernet = Power_Ethernet.SchDoc: VDD_2P5@1.5A, VDD_1V8@1.5A, PowerIn, Ground, VDD_1P0@1.5A, EN_1V8@1.5A, PG_2V5@1.5A, PG_1V8@1.5A, EN_1V0@1.5A, PG_1V0@1.5A, EN_2V5@1.5A, EN_SEQ
U_Power_LED = Power_LED.SchDoc: 3V3_RAIL, PG_3V3@14A_EXP (bidir), PG_5V@10A_EXP (bidir), PG_12@8A_EXP (bidir), PG_ADP1850_0V85_REG1, PG_TPS7A88_1V8_REG2 (bidir), PG_TPS7A88_0V9_REG3, PG_ADP1850_1V2_REG4, PG_VTT_RAM, PG_ADP1741_0V85_REG5, PG_DCDC_Low_curr, PG_48_20V (bidir), PG_PS_LN_3.3V, PG_PS_LTC6952_2, PG_PS_CP_5V0_1, PG_PS_LTC6952_1, PG_MCP_2V5_ETH, PG_1V8@1.5A_ETH, PG_1V0@1.5A_ETH
U_ST1L08_5V_0V6 = ST1L08_5V_0V6.SchDoc: VIN_5V, Vout_VTT_0V6, PG_VTT, EN_VTT, Ground, 3V3_RAIL
U_TPS7A88_3V3_1V8_0V9V@2x1A = TPS7A88_3V3_1V8_0V9V@2x1A.SchDoc: Power_IN1, Ground, 1V8@1A_REG2, 0V9@1A_REG3, PG2_REG3, PG1_REG2, EN2_REG3, EN1_REG2
U_UM78M_12_8V = UM78M_12_8V.SchDoc: Power_In_12V, Power_Out_8V, Ground
XilinxPower = XilinxPower.SchDoc: Ground_SUPPLY, PSIO_VOLTAGE, VCC_1V8_REG8, VCC_0V85_REG1, VCC_1V8_REG2, VCC_0V9_REG3, VCC_1V2_REG4, VCC_0V85_REG5, VCC_1V25_REG6, VCC_1V2_REG9, VCC_3V3_REG7, Vcc_HP, Vcc_HD
Zasilanie CLK = Zasilanie_CLKDistribution.SchDoc: Power_In_12V, Ground, Power_In_5V, Power_In_3.6, 3V3_Rail, VDD_LMK_DIG, Vcc_5V_DAC, WR_GND, CLK_GND, RESET_EXP_SUPP, I2C (harness PWR_Int4), ExpGPIO_IntB, ExpGPIO_IntA, PG_PS_LN_3.3V, PG_PS_LTC6952_2, PG_PS_CP_5V0_1, PG_PS_LTC6952_1

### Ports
3V3_NVME, 3V3_Rail, 5V_Rail, 12V_RAIL, CLK_GND, I2C (harness PWR_Int4), PG_EXP (harness 7_PG), Power_Eth (harness Power_ETH), PSIO_VOLTAGE, PWR_ExtIO_Reset, PWR_Int4 (harness PWR_Int4), PWR_Int6 (harness PWR_Interrupt), RESET_EXP_SUPP, SFP_VCC_3V3, V_PoE+, V_PoE-, Vcc_HD, Vcc_HP, Vcc_HP_HD, VCO_8V, VDD1P8V, VDD_5V_DAC, WR_GND, WR_VDD_DIG_LMK_3.3V

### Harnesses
Power_ETH: VDDA2P5, VDDIO_3.3V, VDDA1P8, VDD1P0
PWR_Int4: Int0, Int1, Int2, Int3, Int4, int5
Power_status: S0, S1, Switch1_Flag, Switch2_Flag, En_Switch1, En_Switch2, S2
7_PG: PG0, PG1, PG2, PG3, PG4, PG5, PG6, PG7

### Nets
GND: P7.1 P9.1 P11.2 R229.2 R456.2 R460.2 R461.2 R464.2 R467.2 R595.2 R837.2 R839.2 R840.2 ; sheet PowerSelector/Ground, sheet HiCurrent/GND_In, sheet LowCurr/Ground_SUPPLY, sheet LowCurr/GND, sheet Zasilanie CLK/Ground, sheet Ram_Power/Ground, sheet XilinxPower/Ground_SUPPLY, sheet Ram/Ground, sheet GND/Ground, sheet U_Power_Ethernet/Ground, sheet I2C_Expander_PWR_Dist/Ground, sheet U_Pomiar_pradu_napiecia_1/Ground, sheet U_Pomiar_pradu_napiecia_2/Ground, sheet U_TPS7A88_3V3_1V8_0V9V@2x1A/Ground, sheet U_ADP1741_3V3_0V85/Ground, sheet U_ST1L08_5V_0V6/Ground  [project net B503_Ground]
0V9@1A_REG3: sheet XilinxPower/VCC_0V9_REG3, sheet U_TPS7A88_3V3_1V8_0V9V@2x1A/0V9@1A_REG3
0V85@2A: sheet XilinxPower/VCC_0V85_REG5, sheet U_ADP1741_3V3_0V85/0V85@2A
1V0@1.5A: sheet U_Power_Ethernet/VDD_1P0@1.5A, port Power_Eth.VDD1P0
1V8@0.5A_ADC_filtered: sheet XilinxPower/VCC_1V8_REG2, sheet U_TPS7A88_3V3_1V8_0V9V@2x1A/1V8@1A_REG2
1V8@1.5A: port VDD1P8V, sheet U_Power_Ethernet/VDD_1V8@1.5A, port Power_Eth.VDDA1P8
2V5@1.5A: sheet Ram_Power/PowerIn_2V5, sheet U_Power_Ethernet/VDD_2P5@1.5A, port Power_Eth.VDDA2P5
3V3_NVMe: port 3V3_NVME, sheet HiCurrent/3V3_NVME
3V3_RAIL: R230.2 R455.1 R458.1 R462.1 R463.2 R468.2 R596.2 ; port SFP_VCC_3V3, port 3V3_Rail, sheet PowerSelector/Vcc_PU, sheet HiCurrent/3V3@10A_util_SFP, sheet HiCurrent/3V3_Rail, sheet LowCurr/EN_1, sheet LowCurr/3V3_RAIL, sheet LowCurr/EN_DCDC, sheet Zasilanie CLK/3V3_Rail, sheet U_Power_Ethernet/PowerIn, sheet I2C_Expander_PWR_Dist/Vcc, sheet U_Pomiar_pradu_napiecia_1/Vin_3V3, sheet U_Pomiar_pradu_napiecia_2/Vin_3V3, sheet U_TPS7A88_3V3_1V8_0V9V@2x1A/Power_IN1, sheet U_ADP1741_3V3_0V85/Power_In_3V3, sheet U_ST1L08_5V_0V6/3V3_RAIL, sheet U_Power_LED/3V3_RAIL  [also labelled 3V3_SFP_UTIL]
5V_LN: port VDD_5V_DAC, sheet Zasilanie CLK/Vcc_5V_DAC
5V_RAIL: port 5V_Rail, sheet HiCurrent/5V@10ARail, sheet Zasilanie CLK/Power_In_5V, sheet U_ST1L08_5V_0V6/VIN_5V
12V_RAIL: port 12V_RAIL, sheet HiCurrent/12@8A, sheet LowCurr/Power_In_12V, sheet Zasilanie CLK/Power_In_12V, sheet U_UM78M_12_8V/Power_In_12V  [project net 12V_LT3042]
ADP1741_3.6V: sheet LowCurr/VSUP_3.6V, sheet Zasilanie CLK/Power_In_3.6
ADP1741_PG: sheet Zasilanie CLK/PG_PS_LN_3.3V, sheet U_Power_LED/PG_PS_LN_3.3V
AGND: port CLK_GND, sheet Zasilanie CLK/CLK_GND, sheet U_UM78M_12_8V/Ground
Battery_PWR: P11.1 ; sheet PowerSelector/Battery_PWR
En_0V85@2A: sheet HiCurrent/PG_1V2@15A, sheet U_ADP1741_3V3_0V85/En_0V85@2A
ETH_VDDIO: port PSIO_VOLTAGE, sheet LowCurr/VSUP_3.3V, sheet XilinxPower/PSIO_VOLTAGE, sheet XilinxPower/VCC_3V3_REG7, sheet U_Power_Ethernet/EN_SEQ, port Power_Eth.VDDIO_3.3V
Ground: port WR_GND, sheet Zasilanie CLK/WR_GND
PG_1V0@1.5A_ETH: sheet U_Power_Ethernet/PG_1V0@1.5A, sheet U_Power_LED/PG_1V0@1.5A_ETH, port PG_EXP.PG3  [project net GPIOa_00.GPIO5]
PG_1V8@1.5A_ETH: sheet U_Power_Ethernet/PG_1V8@1.5A, sheet U_Power_LED/PG_1V8@1.5A_ETH, port PG_EXP.PG2  [project net GPIOa_00.GPIO6]
PG_3V3@14A: R835.1 ; sheet HiCurrent/PG_3V3@14A, port PG_EXP.PG7  [project net PG1_1]
PG_3V3@14A_EXP: R835.2 R837.1 ; sheet I2C_Expander_PWR_Dist/IOB0, sheet U_Power_LED/PG_3V3@14A_EXP
PG_5V@10A: R836.1 ; sheet HiCurrent/PG_5V@10A, port PG_EXP.PG5  [project net PG2_2]
PG_5V@10A_EXP: R836.2 R839.1 ; sheet I2C_Expander_PWR_Dist/IOB1, sheet U_Power_LED/PG_5V@10A_EXP
PG_12@8A: R838.1 ; sheet HiCurrent/PG_12@8A, port PG_EXP.PG4  [project net PG1_2]
PG_12@8A_EXP: R838.2 R840.1 ; sheet I2C_Expander_PWR_Dist/IOB2, sheet U_Power_LED/PG_12@8A_EXP
PG_48_20V: sheet I2C_Expander_PWR_Dist/IOB7, sheet U_Power_48_20V@3A/PG_48_20V, sheet U_Power_LED/PG_48_20V, port PG_EXP.PG6
PG_ADP1741_0V85_REG5: sheet LowCurr/EN_SEQ_LT3504, sheet U_ADP1741_3V3_0V85/PG_0V85@2A, sheet U_Power_LED/PG_ADP1741_0V85_REG5  [project net EN_SEQ_LT3504]
PG_ADP1850_0V85_REG1: sheet HiCurrent/PG_REG_0V85, sheet U_TPS7A88_3V3_1V8_0V9V@2x1A/EN1_REG2, sheet U_Power_LED/PG_ADP1850_0V85_REG1  [project net EN1_TPS]
PG_ADP1850_1V2_REG4: sheet U_ADP1741_3V3_0V85/En_0V85_INDICATOR, sheet U_Power_LED/PG_ADP1850_1V2_REG4
PG_DCDC_Low_curr: sheet LowCurr/DCDC1_PG, sheet U_Power_LED/PG_DCDC_Low_curr, port PG_EXP.PG1  [project net GPIOb_12.GPIO7]
PG_LT3042: sheet Zasilanie CLK/PG_PS_CP_5V0_1, sheet U_Power_LED/PG_PS_CP_5V0_1
PG_MCP_2V5_ETH: sheet HiCurrent/EN_NVME_3V3, sheet U_Power_Ethernet/PG_2V5@1.5A, sheet U_Power_LED/PG_MCP_2V5_ETH  [project net PG_2V5@1.5A]
PG_PS_LTC6952_1: sheet Zasilanie CLK/PG_PS_LTC6952_1, sheet U_Power_LED/PG_PS_LTC6952_1
PG_PS_LTC6952_2: sheet Zasilanie CLK/PG_PS_LTC6952_2, sheet U_Power_LED/PG_PS_LTC6952_2
PG_TPS7A88_0V9_REG3: sheet HiCurrent/EN_1V2@15A, sheet U_TPS7A88_3V3_1V8_0V9V@2x1A/PG2_REG3, sheet U_ST1L08_5V_0V6/EN_VTT, sheet U_Power_LED/PG_TPS7A88_0V9_REG3  [project net PG2_TPS7A8801_0V9]
PG_TPS7A88_1V8_REG2: sheet U_TPS7A88_3V3_1V8_0V9V@2x1A/PG1_REG2, sheet U_TPS7A88_3V3_1V8_0V9V@2x1A/EN2_REG3, sheet U_Power_LED/PG_TPS7A88_1V8_REG2  [project net EN2_TPS]
PG_VTT_RAM: sheet U_ST1L08_5V_0V6/PG_VTT, sheet U_Power_LED/PG_VTT_RAM, port PG_EXP.PG0  [project net GPIOb_02.GPIO4]
Power1_In: P8.1 ; sheet U_Pomiar_pradu_napiecia_1/Vin
Power1_In_CM: sheet PowerSelector/PowerRail1, sheet U_Pomiar_pradu_napiecia_1/Vout
Power2_In: P10.1 ; sheet U_Pomiar_pradu_napiecia_2/Vin
Power2_In_CM: sheet PowerSelector/PowerRail2, sheet U_Pomiar_pradu_napiecia_2/Vout
Power_MUX_Status0: sheet I2C_Expander_PWR_Dist/IOA5, sheet PowerSelector/PowerMuxStatus.S0
Power_MUX_Status1: sheet I2C_Expander_PWR_Dist/IOA6, sheet PowerSelector/PowerMuxStatus.S1
Power_MUX_Status2: sheet I2C_Expander_PWR_Dist/IOA7, sheet PowerSelector/PowerMuxStatus.S2
PWR_ExtIO_INT0: sheet I2C_Expander_PWR_Dist/IntA, port PWR_Int4.Int3
PWR_ExtIO_INT1: sheet I2C_Expander_PWR_Dist/IntB, port PWR_Int4.Int2
PWR_ExtIO_INT2: sheet Zasilanie CLK/ExpGPIO_IntB, port PWR_Int4.Int4
PWR_ExtIO_INT3: sheet Zasilanie CLK/ExpGPIO_IntA, port PWR_Int4.int5
PWR_ExtIO_nReset: port PWR_ExtIO_Reset, sheet I2C_Expander_PWR_Dist/~{RESET}
PWR_OUT_20V: sheet PowerSelector/PWROut, sheet HiCurrent/Power_In_19V
PWR_PoE_20V: sheet PowerSelector/PoE_20V, sheet U_Power_48_20V@3A/Vout_20V@3A  [project net CSN]
PWR_PowerAlert0: sheet I2C_Expander_PWR_Dist/IOA0, sheet U_Pomiar_pradu_napiecia_1/Alert, port PWR_Int4.Int0
PWR_PowerAlert1: sheet I2C_Expander_PWR_Dist/IOA1, sheet U_Pomiar_pradu_napiecia_2/Alert, port PWR_Int4.Int1
PWR_Switch1_En: sheet I2C_Expander_PWR_Dist/IOB3, sheet PowerSelector/PowerMuxStatus.En_Switch1
PWR_Switch1_Flag: sheet I2C_Expander_PWR_Dist/IOB4, sheet PowerSelector/PowerMuxStatus.Switch1_Flag
PWR_Switch2_En: sheet I2C_Expander_PWR_Dist/IOB5, sheet PowerSelector/PowerMuxStatus.En_Switch2
PWR_Switch2_Flag: sheet I2C_Expander_PWR_Dist/IOB6, sheet PowerSelector/PowerMuxStatus.Switch2_Flag
RAM_DDR4_VTT: sheet Ram/RAM_DDR4_VTT, sheet U_ST1L08_5V_0V6/Vout_VTT_0V6
RAM_Vcc1V2: sheet HiCurrent/1V2@15A, sheet Ram_Power/PowerIn_1V2, sheet XilinxPower/VCC_1V2_REG4, sheet Ram/RAM_Vcc1V2
SFP_I2C5.SCL: R457.2 R465.2 R593.2 R597.2 ; sheet U_Pomiar_pradu_napiecia_1/SCL, sheet U_Pomiar_pradu_napiecia_2/SCL
SFP_I2C5.SDA: R459.2 R466.2 R594.2 R598.2 ; sheet U_Pomiar_pradu_napiecia_1/SDA, sheet U_Pomiar_pradu_napiecia_2/SDA
US+_MGTVccAux: port Vcc_HP_HD, port Vcc_HP, port Vcc_HD, sheet LowCurr/VSUP_1V8, sheet XilinxPower/VCC_1V8_REG8, sheet XilinxPower/Vcc_HP, sheet XilinxPower/Vcc_HD
US+_Vcc_PS_DDR_504: sheet LowCurr/VSUP_1V2, sheet XilinxPower/VCC_1V2_REG9
US+_Vcc_PS_IntFp: sheet HiCurrent/0V85@40A, sheet XilinxPower/VCC_0V85_REG1
V_PoE+: port V_PoE+, sheet U_Power_48_20V@3A/Power_IN_PoE
V_PoE-: port V_PoE-, sheet U_Power_48_20V@3A/Ground  [project net PGND]
WR_VDD_DIG_LMK_3.3V: port WR_VDD_DIG_LMK_3.3V, sheet Zasilanie CLK/VDD_LMK_DIG  [project net VDD_DIG]
NetC713_2: port VCO_8V, sheet U_UM78M_12_8V/Power_Out_8V
NetR229_1: R229.1 R230.1 R457.1 R459.1 ; sheet U_Pomiar_pradu_napiecia_1/A0
NetR455_2: R455.2 R456.1 ; sheet I2C_Expander_PWR_Dist/A0
NetR458_2: R458.2 R460.1 ; sheet I2C_Expander_PWR_Dist/A1
NetR461_1: R461.1 R463.1 R465.1 R466.1 ; sheet U_Pomiar_pradu_napiecia_1/A1
NetR462_2: R462.2 R464.1 ; sheet I2C_Expander_PWR_Dist/A2
NetR467_1: R467.1 R468.1 R593.1 R594.1 ; sheet U_Pomiar_pradu_napiecia_2/A0
NetR595_1: R595.1 R596.1 R597.1 R598.1 ; sheet U_Pomiar_pradu_napiecia_2/A1
NetR754_1: port RESET_EXP_SUPP, sheet Zasilanie CLK/RESET_EXP_SUPP

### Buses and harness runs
harness port I2C = sheet HiCurrent/I2C = sheet I2C_Expander_PWR_Dist/I2C = sheet U_Pomiar_pradu_napiecia_1/I2C = sheet U_Pomiar_pradu_napiecia_2/I2C = sheet Zasilanie CLK/I2C
harness port PWR_Int6 = sheet HiCurrent/Interrupt0

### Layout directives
net class Power_Line_40A: US+_Vcc_PS_IntFp
net class Ground: B503_Ground

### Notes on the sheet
- (near P11) Złącze na baterie
- 0x42
- (near R467) HEX
  0x80
- HEX
  0x82
- *6,5V >ENh> 1,1V
- RAM

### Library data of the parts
P11 = Header 2: 00000005000HDR ASSY F/L SQ STR; Manufacturer: TE Connectivity; Manufacturer Part Number: 640456-2; Connector Type: Connector,Pin,Plug,Header; Shrouded: No (Without); Contact Current Rating: 5A; Connector System: Wire-to-Board; Plating Thickness: 3.81um; PCB Mount Retention: Without; Contact Resistance: 6mR; Max Voltage Rating (AC): 250V; Number of Positions: 2; Gender: Male; Contact Style: Straight; Mating Connector Lock: Yes (With); PCB Mounting Orientation: Vertical; Circuit Application: Signal; Pitch: 2.54mm; PCB Thickness: 0.063inch; Tail Length: 0.14inch; Contact Post Length: 3.56mm; Approvals: CSA
R229 R230 R455 R457-R459 R461-R463 R465-R468 R593-R598 = Resistor: PANASONIC - ERJ-2RKF1001X - SMD Chip Resistor, 0402 [1005 Metric], 1 kohm, ERJ2R Series, 50 V, Thick Film, 100 mW; Temperature Coefficient: 100ppm/°C; Tolerance: 1%; Voltage Rating (DC): 50V; Power Rating: 100mW
R456 R460 R464 = Resistor: as R425 on sheet SPI_Muxes
R835 R836 R838 = Resistor: Manufacturer 1: Yageo; Manufacturer Part Number 1: RC0402FR-0710KL; Tolerance: 1%; Temperature Coefficient: 100ppm/°C; Voltage Rating: 50V; Power Rating: 62.5mW
R837 R839 R840 = Resistor: Manufacturer: Panasonic; Manufacturer Part Number: ERJ-2RKF2002X; Power Rating: 100mW; Tolerance: 1%; Voltage Rating: 50V; Temperature Coefficient: 100ppm/°C

## Sheet Power_Switch.SchDoc: Power_Switch
size A3; Organization: Altium Limited; Address1: L3, 12a Rodborough Rd; Address2: Frenchs Forest; Address3: NSW; Address4: Australia 2086
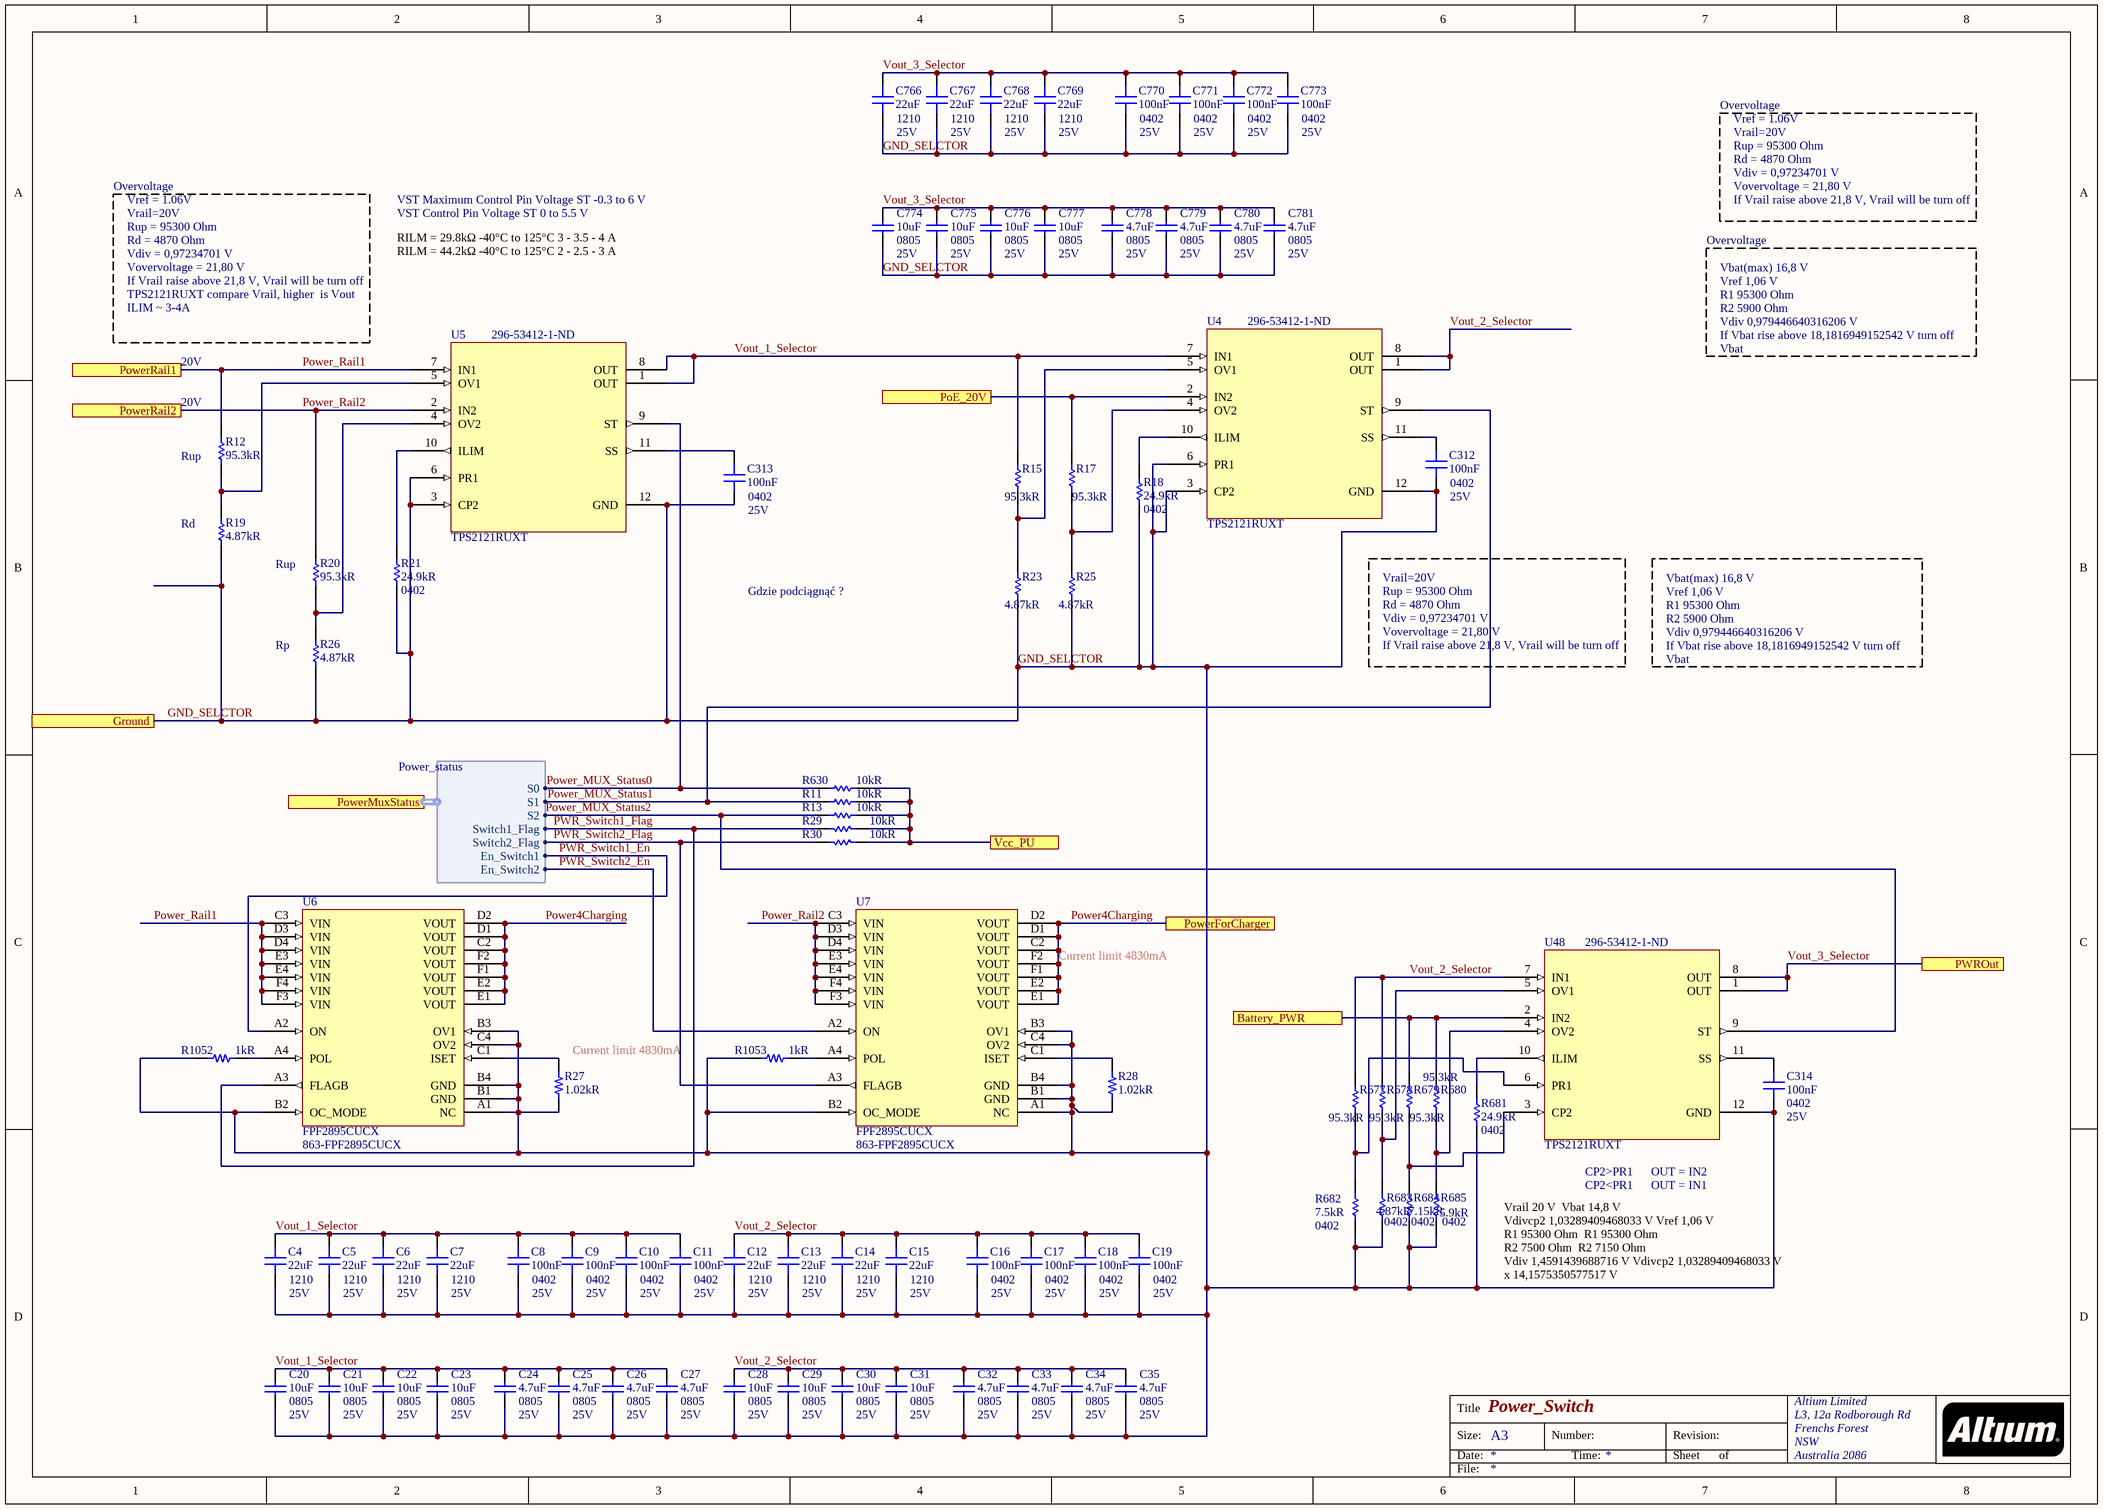
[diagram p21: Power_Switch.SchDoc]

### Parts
C4  22uF  Case/Package: 1210  Voltage Rating: 25V  [CAP 1210/3225 - 1MM]
C5  22uF  Case/Package: 1210  Voltage Rating: 25V  [CAP 1210/3225 - 1MM]
C6  22uF  Case/Package: 1210  Voltage Rating: 25V  [CAP 1210/3225 - 1MM]
C7  22uF  Case/Package: 1210  Voltage Rating: 25V  [CAP 1210/3225 - 1MM]
C8  100nF  Case/Package: 0402  Voltage Rating: 25V  [CAP 0402/1005 KK]
C9  100nF  Case/Package: 0402  Voltage Rating: 25V  [CAP 0402/1005 KK]
C10  100nF  Case/Package: 0402  Voltage Rating: 25V  [CAP 0402/1005 KK]
C11  100nF  Case/Package: 0402  Voltage Rating: 25V  [CAP 0402/1005 KK]
C12  22uF  Case/Package: 1210  Voltage Rating: 25V  [CAP 1210/3225 - 1MM]
C13  22uF  Case/Package: 1210  Voltage Rating: 25V  [CAP 1210/3225 - 1MM]
C14  22uF  Case/Package: 1210  Voltage Rating: 25V  [CAP 1210/3225 - 1MM]
C15  22uF  Case/Package: 1210  Voltage Rating: 25V  [CAP 1210/3225 - 1MM]
C16  100nF  Case/Package: 0402  Voltage Rating: 25V  [CAP 0402/1005 KK]
C17  100nF  Case/Package: 0402  Voltage Rating: 25V  [CAP 0402/1005 KK]
C18  100nF  Case/Package: 0402  Voltage Rating: 25V  [CAP 0402/1005 KK]
C19  100nF  Case/Package: 0402  Voltage Rating: 25V  [CAP 0402/1005 KK]
C20  10uF  Case/Package: 0805  Voltage Rating: 25V  [CAP 0805/2012 RF]
C21  10uF  Case/Package: 0805  Voltage Rating: 25V  [CAP 0805/2012 RF]
C22  10uF  Case/Package: 0805  Voltage Rating: 25V  [CAP 0805/2012 RF]
C23  10uF  Case/Package: 0805  Voltage Rating: 25V  [CAP 0805/2012 RF]
C24  4.7uF  Case/Package: 0805  Voltage Rating: 25V  [CAP 0805/2012 RF]
C25  4.7uF  Case/Package: 0805  Voltage Rating: 25V  [CAP 0805/2012 RF]
C26  4.7uF  Case/Package: 0805  Voltage Rating: 25V  [CAP 0805/2012 RF]
C27  4.7uF  Case/Package: 0805  Voltage Rating: 25V  [CAP 0805/2012 RF]
C28  10uF  Case/Package: 0805  Voltage Rating: 25V  [CAP 0805/2012 RF]
C29  10uF  Case/Package: 0805  Voltage Rating: 25V  [CAP 0805/2012 RF]
C30  10uF  Case/Package: 0805  Voltage Rating: 25V  [CAP 0805/2012 RF]
C31  10uF  Case/Package: 0805  Voltage Rating: 25V  [CAP 0805/2012 RF]
C32  4.7uF  Case/Package: 0805  Voltage Rating: 25V  [CAP 0805/2012 RF]
C33  4.7uF  Case/Package: 0805  Voltage Rating: 25V  [CAP 0805/2012 RF]
C34  4.7uF  Case/Package: 0805  Voltage Rating: 25V  [CAP 0805/2012 RF]
C35  4.7uF  Case/Package: 0805  Voltage Rating: 25V  [CAP 0805/2012 RF]
C312  100nF  Case/Package: 0402  Voltage Rating: 25V  [CAP 0402/1005 KK]
C313  100nF  Case/Package: 0402  Voltage Rating: 25V  [CAP 0402/1005 KK]
C314  100nF  Case/Package: 0402  Voltage Rating: 25V  [CAP 0402/1005 KK]
C766  22uF  Case/Package: 1210  Voltage Rating: 25V  [CAP 1210/3225 - 1MM]
C767  22uF  Case/Package: 1210  Voltage Rating: 25V  [CAP 1210/3225 - 1MM]
C768  22uF  Case/Package: 1210  Voltage Rating: 25V  [CAP 1210/3225 - 1MM]
C769  22uF  Case/Package: 1210  Voltage Rating: 25V  [CAP 1210/3225 - 1MM]
C770  100nF  Case/Package: 0402  Voltage Rating: 25V  [CAP 0402/1005 KK]
C771  100nF  Case/Package: 0402  Voltage Rating: 25V  [CAP 0402/1005 KK]
C772  100nF  Case/Package: 0402  Voltage Rating: 25V  [CAP 0402/1005 KK]
C773  100nF  Case/Package: 0402  Voltage Rating: 25V  [CAP 0402/1005 KK]
C774  10uF  Case/Package: 0805  Voltage Rating: 25V  [CAP 0805/2012 RF]
C775  10uF  Case/Package: 0805  Voltage Rating: 25V  [CAP 0805/2012 RF]
C776  10uF  Case/Package: 0805  Voltage Rating: 25V  [CAP 0805/2012 RF]
C777  10uF  Case/Package: 0805  Voltage Rating: 25V  [CAP 0805/2012 RF]
C778  4.7uF  Case/Package: 0805  Voltage Rating: 25V  [CAP 0805/2012 RF]
C779  4.7uF  Case/Package: 0805  Voltage Rating: 25V  [CAP 0805/2012 RF]
C780  4.7uF  Case/Package: 0805  Voltage Rating: 25V  [CAP 0805/2012 RF]
C781  4.7uF  Case/Package: 0805  Voltage Rating: 25V  [CAP 0805/2012 RF]
R11  10kR  [RES 0402/1005 RF KK]
R12  95.3kR  [RES 0402/1005 RF KK]
R13  10kR  [RES 0402/1005 RF KK]
R15  95.3kR  [RES 0402/1005 RF KK]
R17  95.3kR  [RES 0402/1005 RF KK]
R18  24.9kR  Case/Package: 0402  [RES 0402/1005 RF KK]
R19  4.87kR  [RES 0402/1005 RF KK]
R20  95.3kR  [RES 0402/1005 RF KK]
R21  24.9kR  Case/Package: 0402  [RES 0402/1005 RF KK]
R23  4.87kR  [RES 0402/1005 RF KK]
R25  4.87kR  [RES 0402/1005 RF KK]
R26  4.87kR  [RES 0402/1005 RF KK]
R27  1.02kR  [RES 0402/1005 RF KK]
R28  1.02kR  [RES 0402/1005 RF KK]
R29  10kR  [RES 0402/1005 RF KK]
R30  10kR  [RES 0402/1005 RF KK]
R630  10kR  [RES 0402/1005 RF KK]
R677  95.3kR  [RES 0402/1005 RF KK]
R678  95.3kR  [RES 0402/1005 RF KK]
R679  95.3kR  [RES 0402/1005 RF KK]
R680  95.3kR  [RES 0402/1005 RF KK]
R681  24.9kR  Case/Package: 0402  [RES 0402/1005 RF KK]
R682  7.5kR  Case Code (Imperial): 0402  [RES 0402/1005 RF KK]
R683  4.87kR  Case/Package: 0402  [RES 0402/1005 RF KK]
R684  7.15kR  Case/Package: 0402  [RES 0402/1005 RF KK]
R685  5.9kR  Case Code (Imperial): 0402  [RES 0402/1005 RF KK]
R1052  1kR  [RES 0402/1005 RF KK]
R1053  1kR  [RES 0402/1005 RF KK]
U4  TPS2121RUXT  Supplier Part Number 1: 296-53412-1-ND  [TPS212x]
U5  TPS2121RUXT  Supplier Part Number 1: 296-53412-1-ND  [TPS212x]
U6  FPF2895CUCX  Supplier Part Number 1: 863-FPF2895CUCX  [FPF2895C-D]
U7  FPF2895CUCX  Supplier Part Number 1: 863-FPF2895CUCX  [FPF2895C-D]
U48  TPS2121RUXT  Supplier Part Number 1: 296-53412-1-ND  [TPS212x]

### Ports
Battery_PWR, Ground, PoE_20V, PowerForCharger, PowerMuxStatus (harness Power_status), PowerRail1, PowerRail2, PWROut, Vcc_PU

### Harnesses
Power_status: S0, S1, Switch1_Flag, Switch2_Flag, En_Switch1, En_Switch2, S2

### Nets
GND_SELCTOR: C4.2 C5.2 C6.2 C7.2 C8.1 C9.1 C10.1 C11.1 C12.2 C13.2 C14.2 C15.2 C16.1 C17.1 C18.1 C19.1 C20.1 C21.1 C22.1 C23.1 C24.1 C25.1 C26.1 C27.1 C28.1 C29.1 C30.1 C31.1 C32.1 C33.1 C34.1 C35.1 C312.1 C313.1 C314.2 C766.2 C767.2 C768.2 C769.2 C770.1 C771.1 C772.1 C773.1 C774.1 C775.1 C776.1 C777.1 C778.1 C779.1 C780.1 C781.1 R18.1 R19.1 R21.1 R23.1 R25.1 R26.1 R27.1 R28.2 R681.1 R682.1 R683.1 R684.1 R685.1 R1052.2 R1053.2 U4.3(CP2) U4.6(PR1) U4.12(GND) U5.3(CP2) U5.6(PR1) U5.12(GND) U6.A1(NC) U6.B1(GND) U6.B2(OC_MODE) U6.B3(OV1) U6.B4(GND) U6.C4(OV2) U7.A1(NC) U7.B1(GND) U7.B2(OC_MODE) U7.B3(OV1) U7.B4(GND) U7.C4(OV2) U48.12(GND) ; port Ground  [project net B503_Ground]
3V3_RAIL: R11.2 R13.1 R29.2 R30.2 R630.1 ; port Vcc_PU
Battery_PWR: R679.2 R680.2 U48.2(IN2) ; port Battery_PWR
CSN: R17.2 U4.2(IN2) ; port PoE_20V
Power4Charging: U6.C2(VOUT) U6.D1(VOUT) U6.D2(VOUT) U6.E1(VOUT) U6.E2(VOUT) U6.F1(VOUT) U6.F2(VOUT) U7.C2(VOUT) U7.D1(VOUT) U7.D2(VOUT) U7.E1(VOUT) U7.E2(VOUT) U7.F1(VOUT) U7.F2(VOUT) ; port PowerForCharger
Power_MUX_Status0: R630.2 U5.9(ST) ; port PowerMuxStatus.S0
Power_MUX_Status1: R11.1 U4.9(ST) ; port PowerMuxStatus.S1
Power_MUX_Status2: R13.2 U48.9(ST) ; port PowerMuxStatus.S2
Power_Rail1: R12.2 U5.7(IN1) U6.C3(VIN) U6.D3(VIN) U6.D4(VIN) U6.E3(VIN) U6.E4(VIN) U6.F3(VIN) U6.F4(VIN) ; port PowerRail1  [project net Power1_In_CM]
Power_Rail2: R20.2 U5.2(IN2) U7.C3(VIN) U7.D3(VIN) U7.D4(VIN) U7.E3(VIN) U7.E4(VIN) U7.F3(VIN) U7.F4(VIN) ; port PowerRail2  [project net Power2_In_CM]
PWR_Switch1_En: U6.A2(ON) ; port PowerMuxStatus.En_Switch1
PWR_Switch1_Flag: R29.1 U6.A3(FLAGB) ; port PowerMuxStatus.Switch1_Flag
PWR_Switch2_En: U7.A2(ON) ; port PowerMuxStatus.En_Switch2
PWR_Switch2_Flag: R30.1 U7.A3(FLAGB) ; port PowerMuxStatus.Switch2_Flag
Vout_1_Selector: C4.1 C5.1 C6.1 C7.1 C8.2 C9.2 C10.2 C11.2 C20.2 C21.2 C22.2 C23.2 C24.2 C25.2 C26.2 C27.2 R15.2 U4.7(IN1) U5.1(OUT) U5.8(OUT)
Vout_2_Selector: C12.1 C13.1 C14.1 C15.1 C16.2 C17.2 C18.2 C19.2 C28.2 C29.2 C30.2 C31.2 C32.2 C33.2 C34.2 C35.2 R677.2 R678.2 U4.1(OUT) U4.8(OUT) U48.7(IN1)
Vout_3_Selector: C766.1 C767.1 C768.1 C769.1 C770.2 C771.2 C772.2 C773.2 C774.2 C775.2 C776.2 C777.2 C778.2 C779.2 C780.2 C781.2 U48.1(OUT) U48.8(OUT) ; port PWROut  [project net PWR_OUT_20V]
NetC312_2: C312.2 U4.11(SS)
NetC313_2: C313.2 U5.11(SS)
NetC314_1: C314.1 U48.11(SS)
NetR12_1: R12.1 R19.2 U5.5(OV1)
NetR15_1: R15.1 R23.2 U4.5(OV1)
NetR17_1: R17.1 R25.2 U4.4(OV2)
NetR18_2: R18.2 U4.10(ILIM)
NetR20_1: R20.1 R26.2 U5.4(OV2)
NetR21_2: R21.2 U5.10(ILIM)
NetR27_2: R27.2 U6.C1(ISET)
NetR28_1: R28.1 U7.C1(ISET)
NetR677_1: R677.1 R682.2 U48.6(PR1)
NetR678_1: R678.1 R683.2 U48.5(OV1)
NetR679_1: R679.1 R684.2 U48.3(CP2)
NetR680_1: R680.1 R685.2 U48.4(OV2)
NetR681_2: R681.2 U48.10(ILIM)
NetR1052_1: R1052.1 U6.A4(POL)
NetR1053_1: R1053.1 U7.A4(POL)

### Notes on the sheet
- Overvoltage
- Vref = 1.06V
- Vrail=20V
- Rup = 95300 Ohm
- Rd = 4870 Ohm
- Vdiv = 0,97234701 V
- VST Maximum Control Pin Voltage ST -0.3 to 6 V
- VST Control Pin Voltage ST 0 to 5.5 V
- Vovervoltage = 21,80 V
- If Vrail raise above 21,8 V, Vrail will be turn off
- TPS2121RUXT compare Vrail, higher  is Vout
- ILIM ~ 3-4A
- RILM = 29.8kΩ -40°C to 125°C 3 - 3.5 - 4 A
  RILM = 44.2kΩ -40°C to 125°C 2 - 2.5 - 3 A
- 20V
- Vbat(max)	16,8	V
  Vref	1,06	V
  R1	95300	Ohm
  R2	5900	Ohm
  Vdiv	0,979446640316206	V
  If Vbat rise above 18,1816949152542 V turn off Vbat
- (near R12) 20V
- (near R12) Rup
- (near R19) Rd
- (near R20) Rup
- (near R26) Rp
- Gdzie podciągnąć ?
- (near U7) Current limit 4830mA
- (near R27) Current limit 4830mA
- CP2>PR1      OUT = IN2
- CP2<PR1      OUT = IN1
- Vrail	20	V		Vbat	14,8	V
  Vdivcp2	1,03289409468033	V	Vref	1,06	V
  R1	95300	Ohm		R1	95300	Ohm
  R2	7500	Ohm		R2	7150	Ohm
  Vdiv	1,4591439688716	V	Vdivcp2	1,03289409468033	V
  x	14,1575350577517	V

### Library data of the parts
C4-C7 C12-C15 C766-C769 = Capacitor: Manufacturer: Samsung; Manufacturer Part Number: CL32A226KAJNNNE; Material: Ceramic; Tolerance: 10%; Dielectric: X5R
C8-C11 C16-C19 C312-C314 C770-C773 = Capacitor: Manufacturer: Murata; Manufacturer Part Number: GRM155R71E104KE14J; Tolerance: 10%; Dielectric: X7R
C20-C23 C28-C31 C774-C777 = Capacitor: CAP CER 10UF 25V X5R 0805; Manufacturer: KEMET; Manufacturer Part Number: C0805C106K3PACTU; Dielectric Material: Ceramic; Dissipation Factor: 10%
C24-C27 C32-C35 C778-C781 = Capacitor: CAP CER 4.7UF 25V X5R 0805; Manufacturer: Murata; Manufacturer Part Number: GRM219R61E475KA73D; Material: Ceramic; Tolerance: 10%
R11 R13 R29 R30 R630 = Resistor: as R835 on sheet Power_Distribution
R12 R15 R17 R20 R677-R680 = Resistor: Manufacturer 1: Yageo; Manufacturer Part Number 1: RC0402FR-0795K3L; Tolerance: 1%; Voltage Rating (DC): 50V; Power Rating: 62.5mW; Temperature Coefficient: 100ppm/°C; Max Power Dissipation: 63mW
R18 R21 R681 = Resistor: RES SMD 24.9KOHM 0.1% 1/16W 0402; Manufacturer: Panasonic; Manufacturer Part Number: ERA-2AEB2492X; Power Rating: 63mW; Voltage Rating: 25V; Temperature Coefficient: 25ppm/°C; Voltage Rating (DC): 50V
R19 R23 R25 R26 R683 = Resistor: Manufacturer 1: Yageo; Manufacturer Part Number 1: RC0402FR-074K87L; Power Rating: 62.5mW; Tolerance: 1%; Voltage Rating: 50V; Temperature Coefficient: 100ppm/°C; Max Power Dissipation: 63mW
R27 R28 = Resistor: as R182 on sheet Power4HiSpeed
R682 = Resistor: RES SMD 7.5K OHM 0.5% 1/16W 0402; Manufacturer: Susumu; Manufacturer Part Number: RR0510P-752-D; Power Rating: 62.5mW; Voltage Rating: 25V; Max Power Dissipation: 63mW; Temperature Coefficient: 25ppm/°C; Voltage Rating (DC): 50V
R684 = Resistor: Manufacturer 1: Yageo; Manufacturer Part Number 1: RC0402FR-077K15L; Tolerance: 1%; Power Rating: 62.5mW; Voltage Rating: 50V; Temperature Coefficient: 100ppm/°C; Max Power Dissipation: 63mW
R685 = Resistor: Manufacturer: Stackpole Electronics; Manufacturer Part Number: RMCF0402FT5K90; Tolerance: 1%; Max Power Dissipation: 63mW; Temperature Coefficient: 100ppm/°C
R1052 R1053 = Resistor: as R231-R240 on sheet SPI_Muxes
U4 U5 U48 = TPS2121RUXT: Manufacturer 1: Texas Instruments
U6 U7 = FPF2895CUCX: as U17 on sheet Power4HiSpeed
